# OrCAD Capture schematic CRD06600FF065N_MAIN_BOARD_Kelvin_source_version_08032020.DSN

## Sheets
1 P1 PFC: size A2; title: 6.6kW HD Bi-directional OBC Main Board; rev: 3; note: P/N: CRD06600FF065N
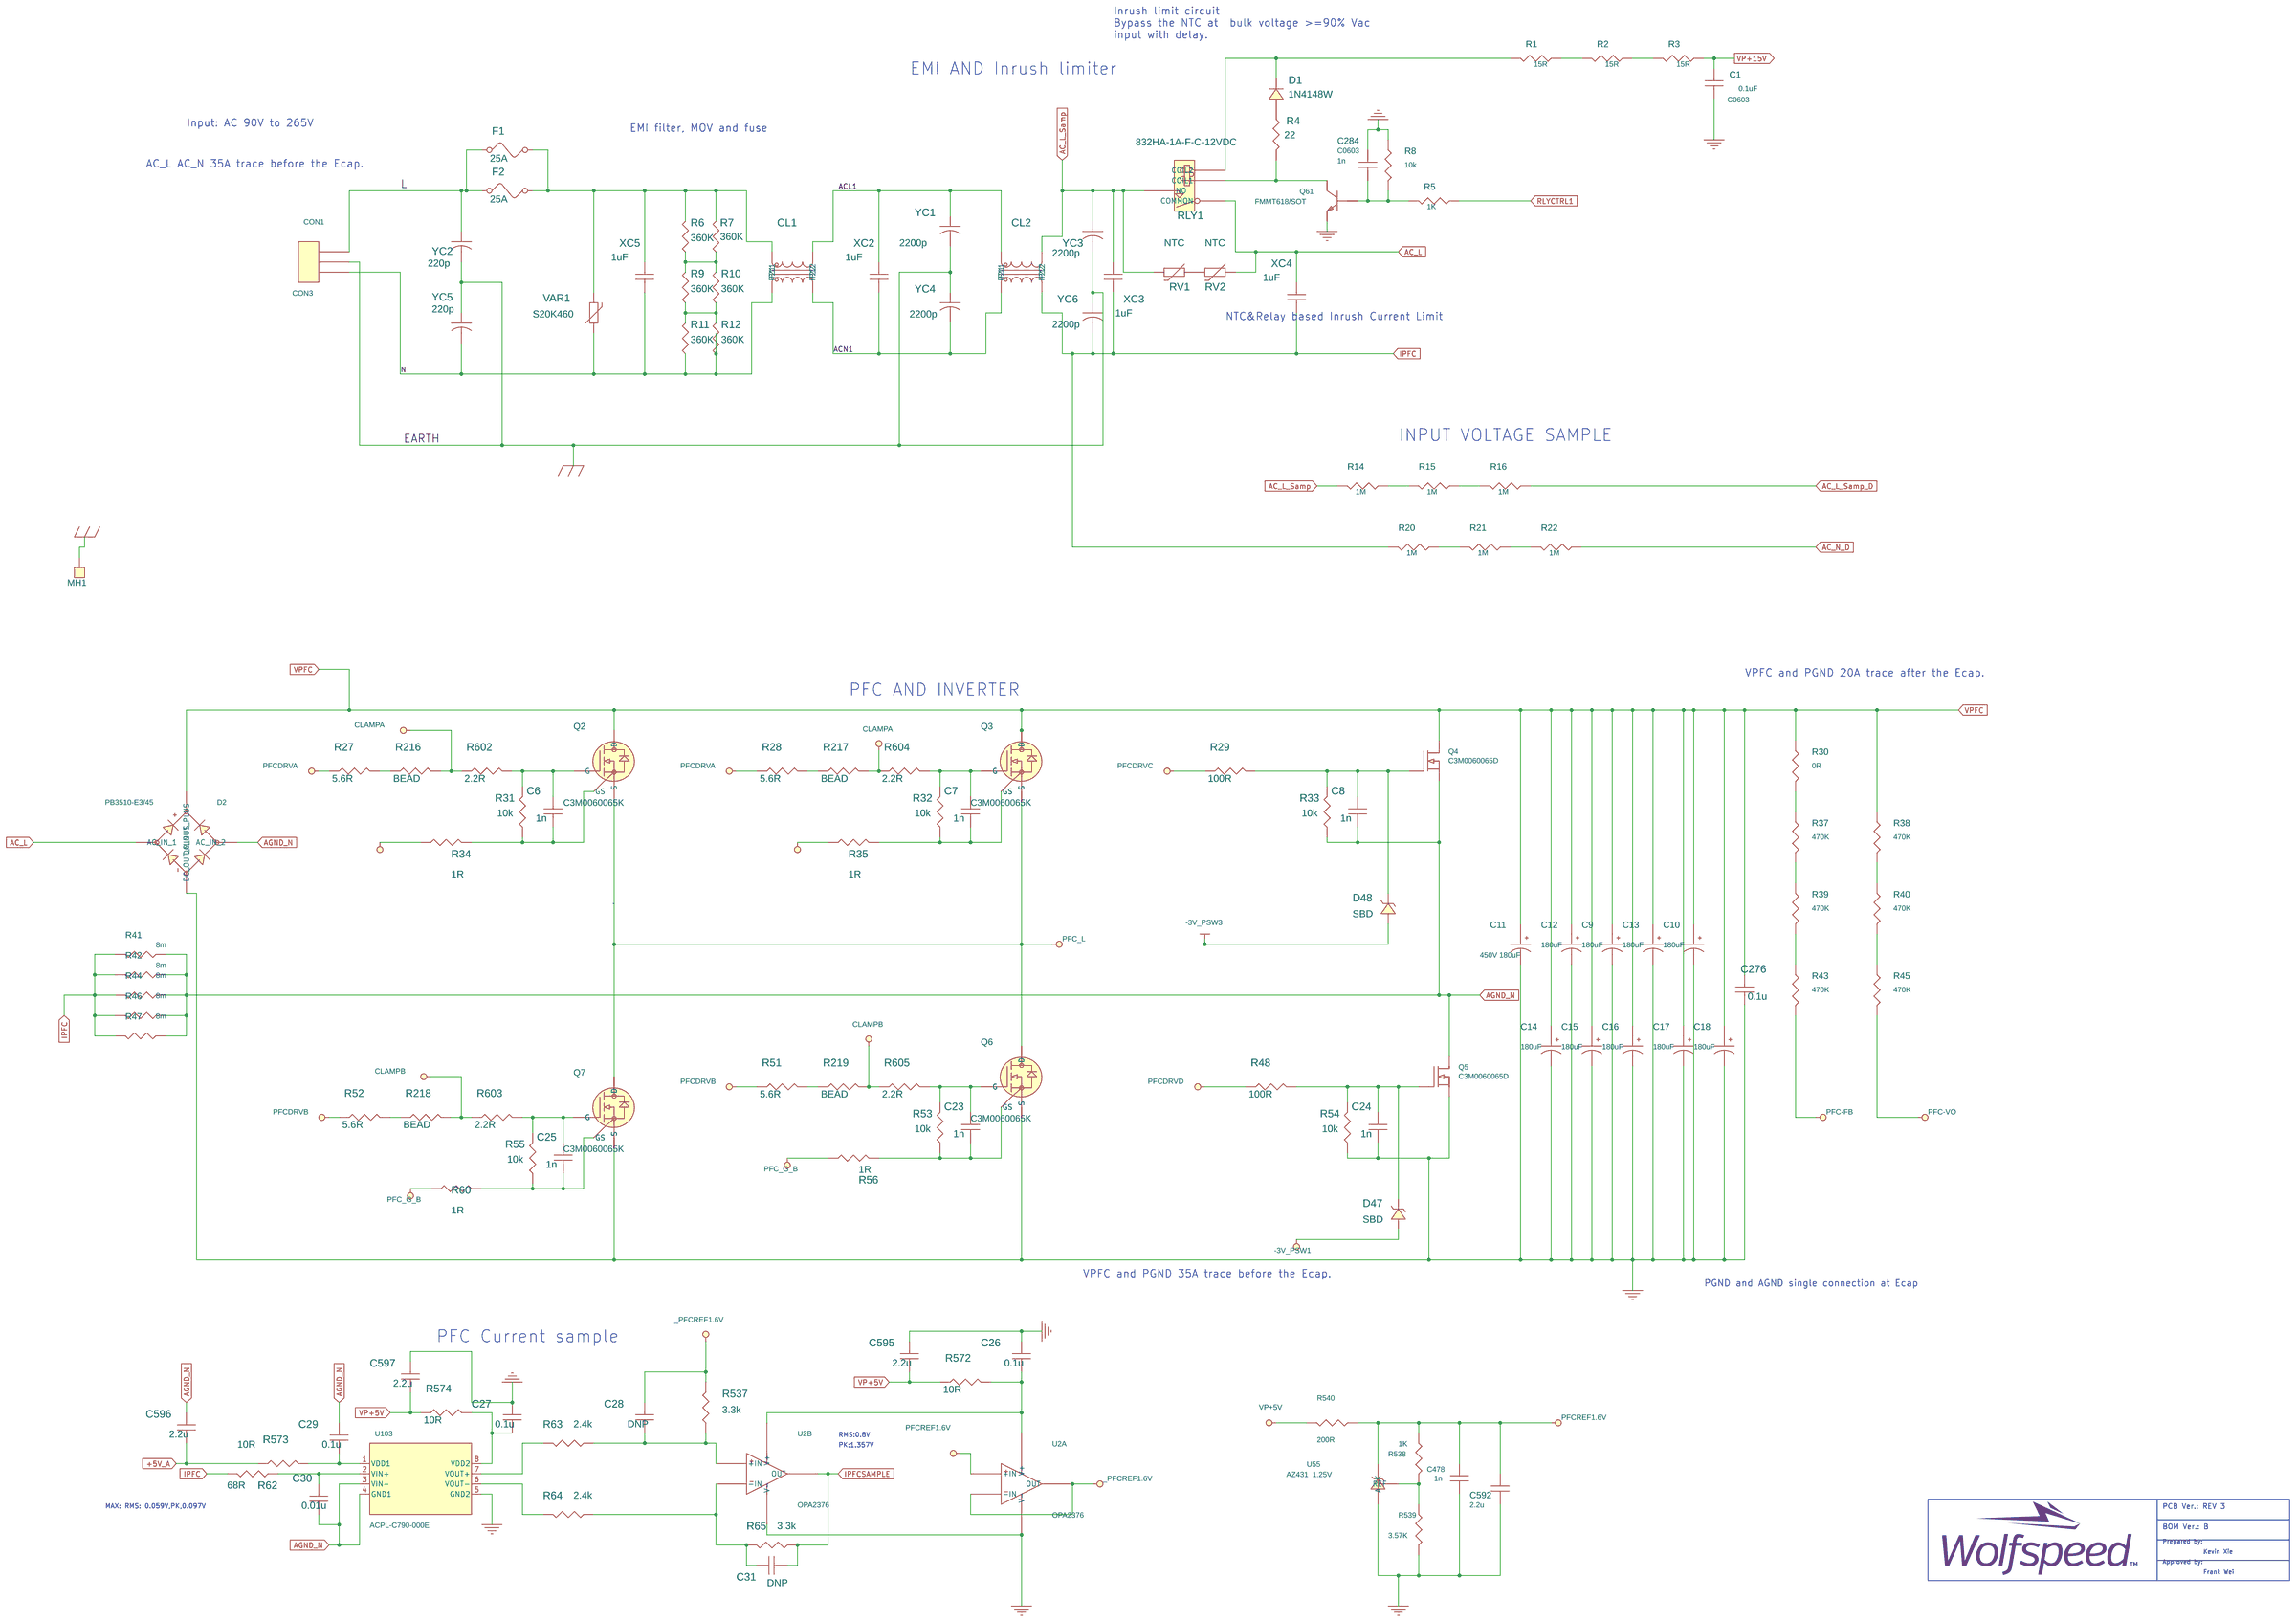
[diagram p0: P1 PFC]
2 P2 PFC Gate Driver: size A2
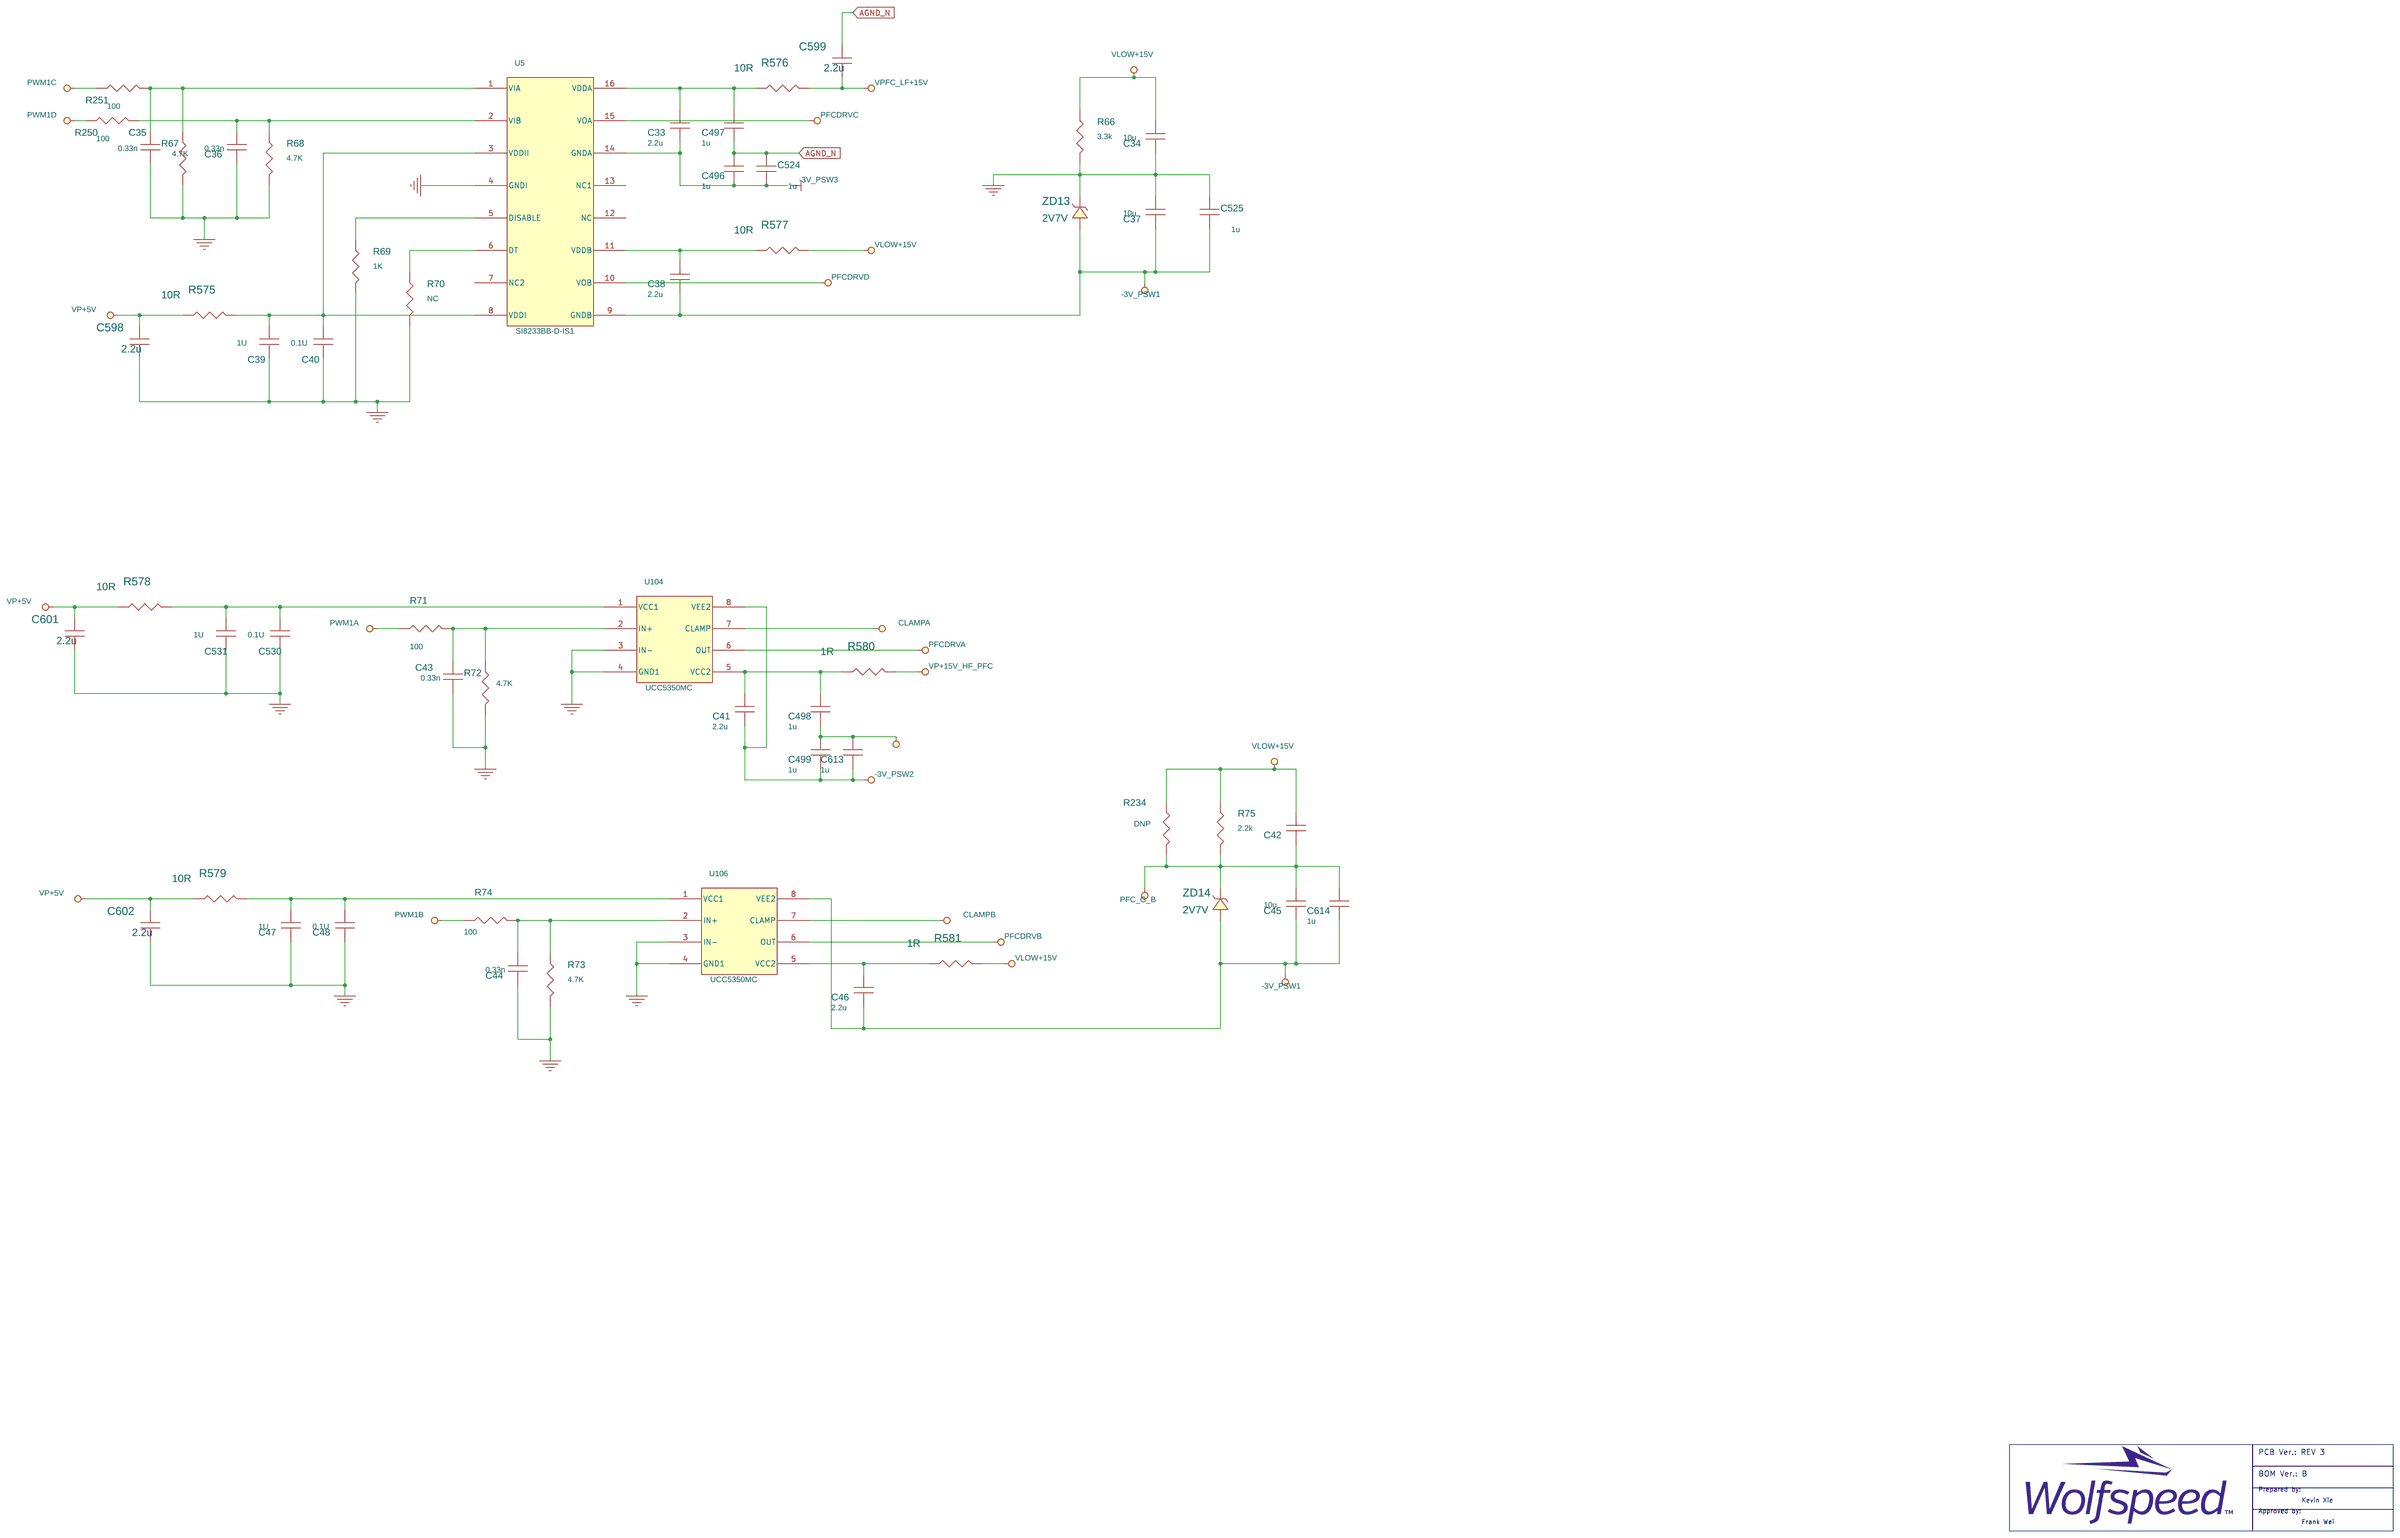
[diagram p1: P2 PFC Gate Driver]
3 P4 Main DCDC: size A1
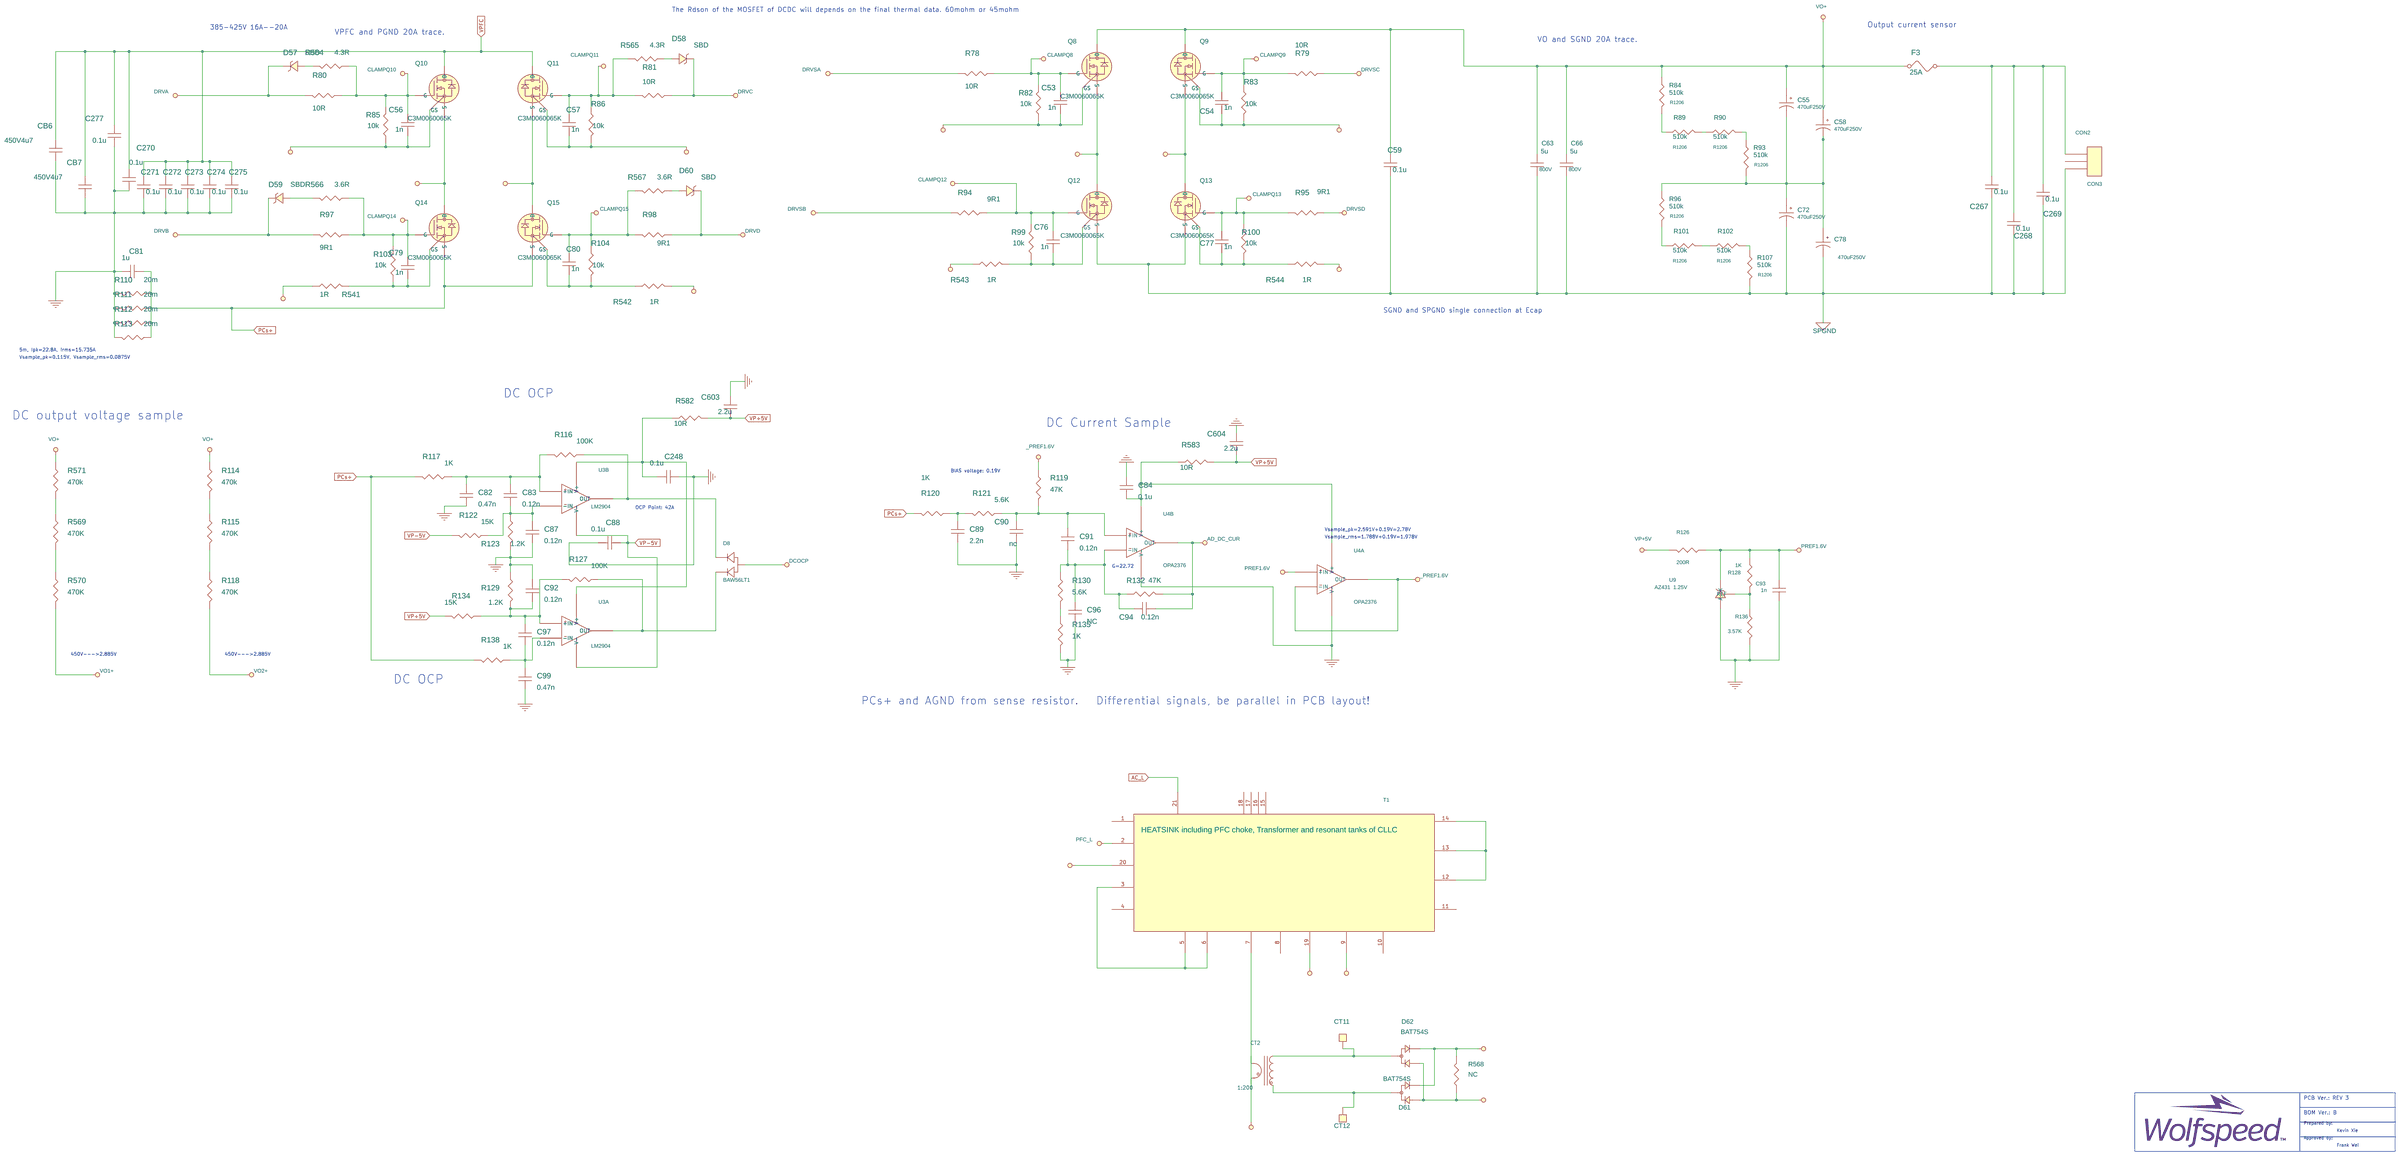
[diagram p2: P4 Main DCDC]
4 P5 Isolation Interface: size A3
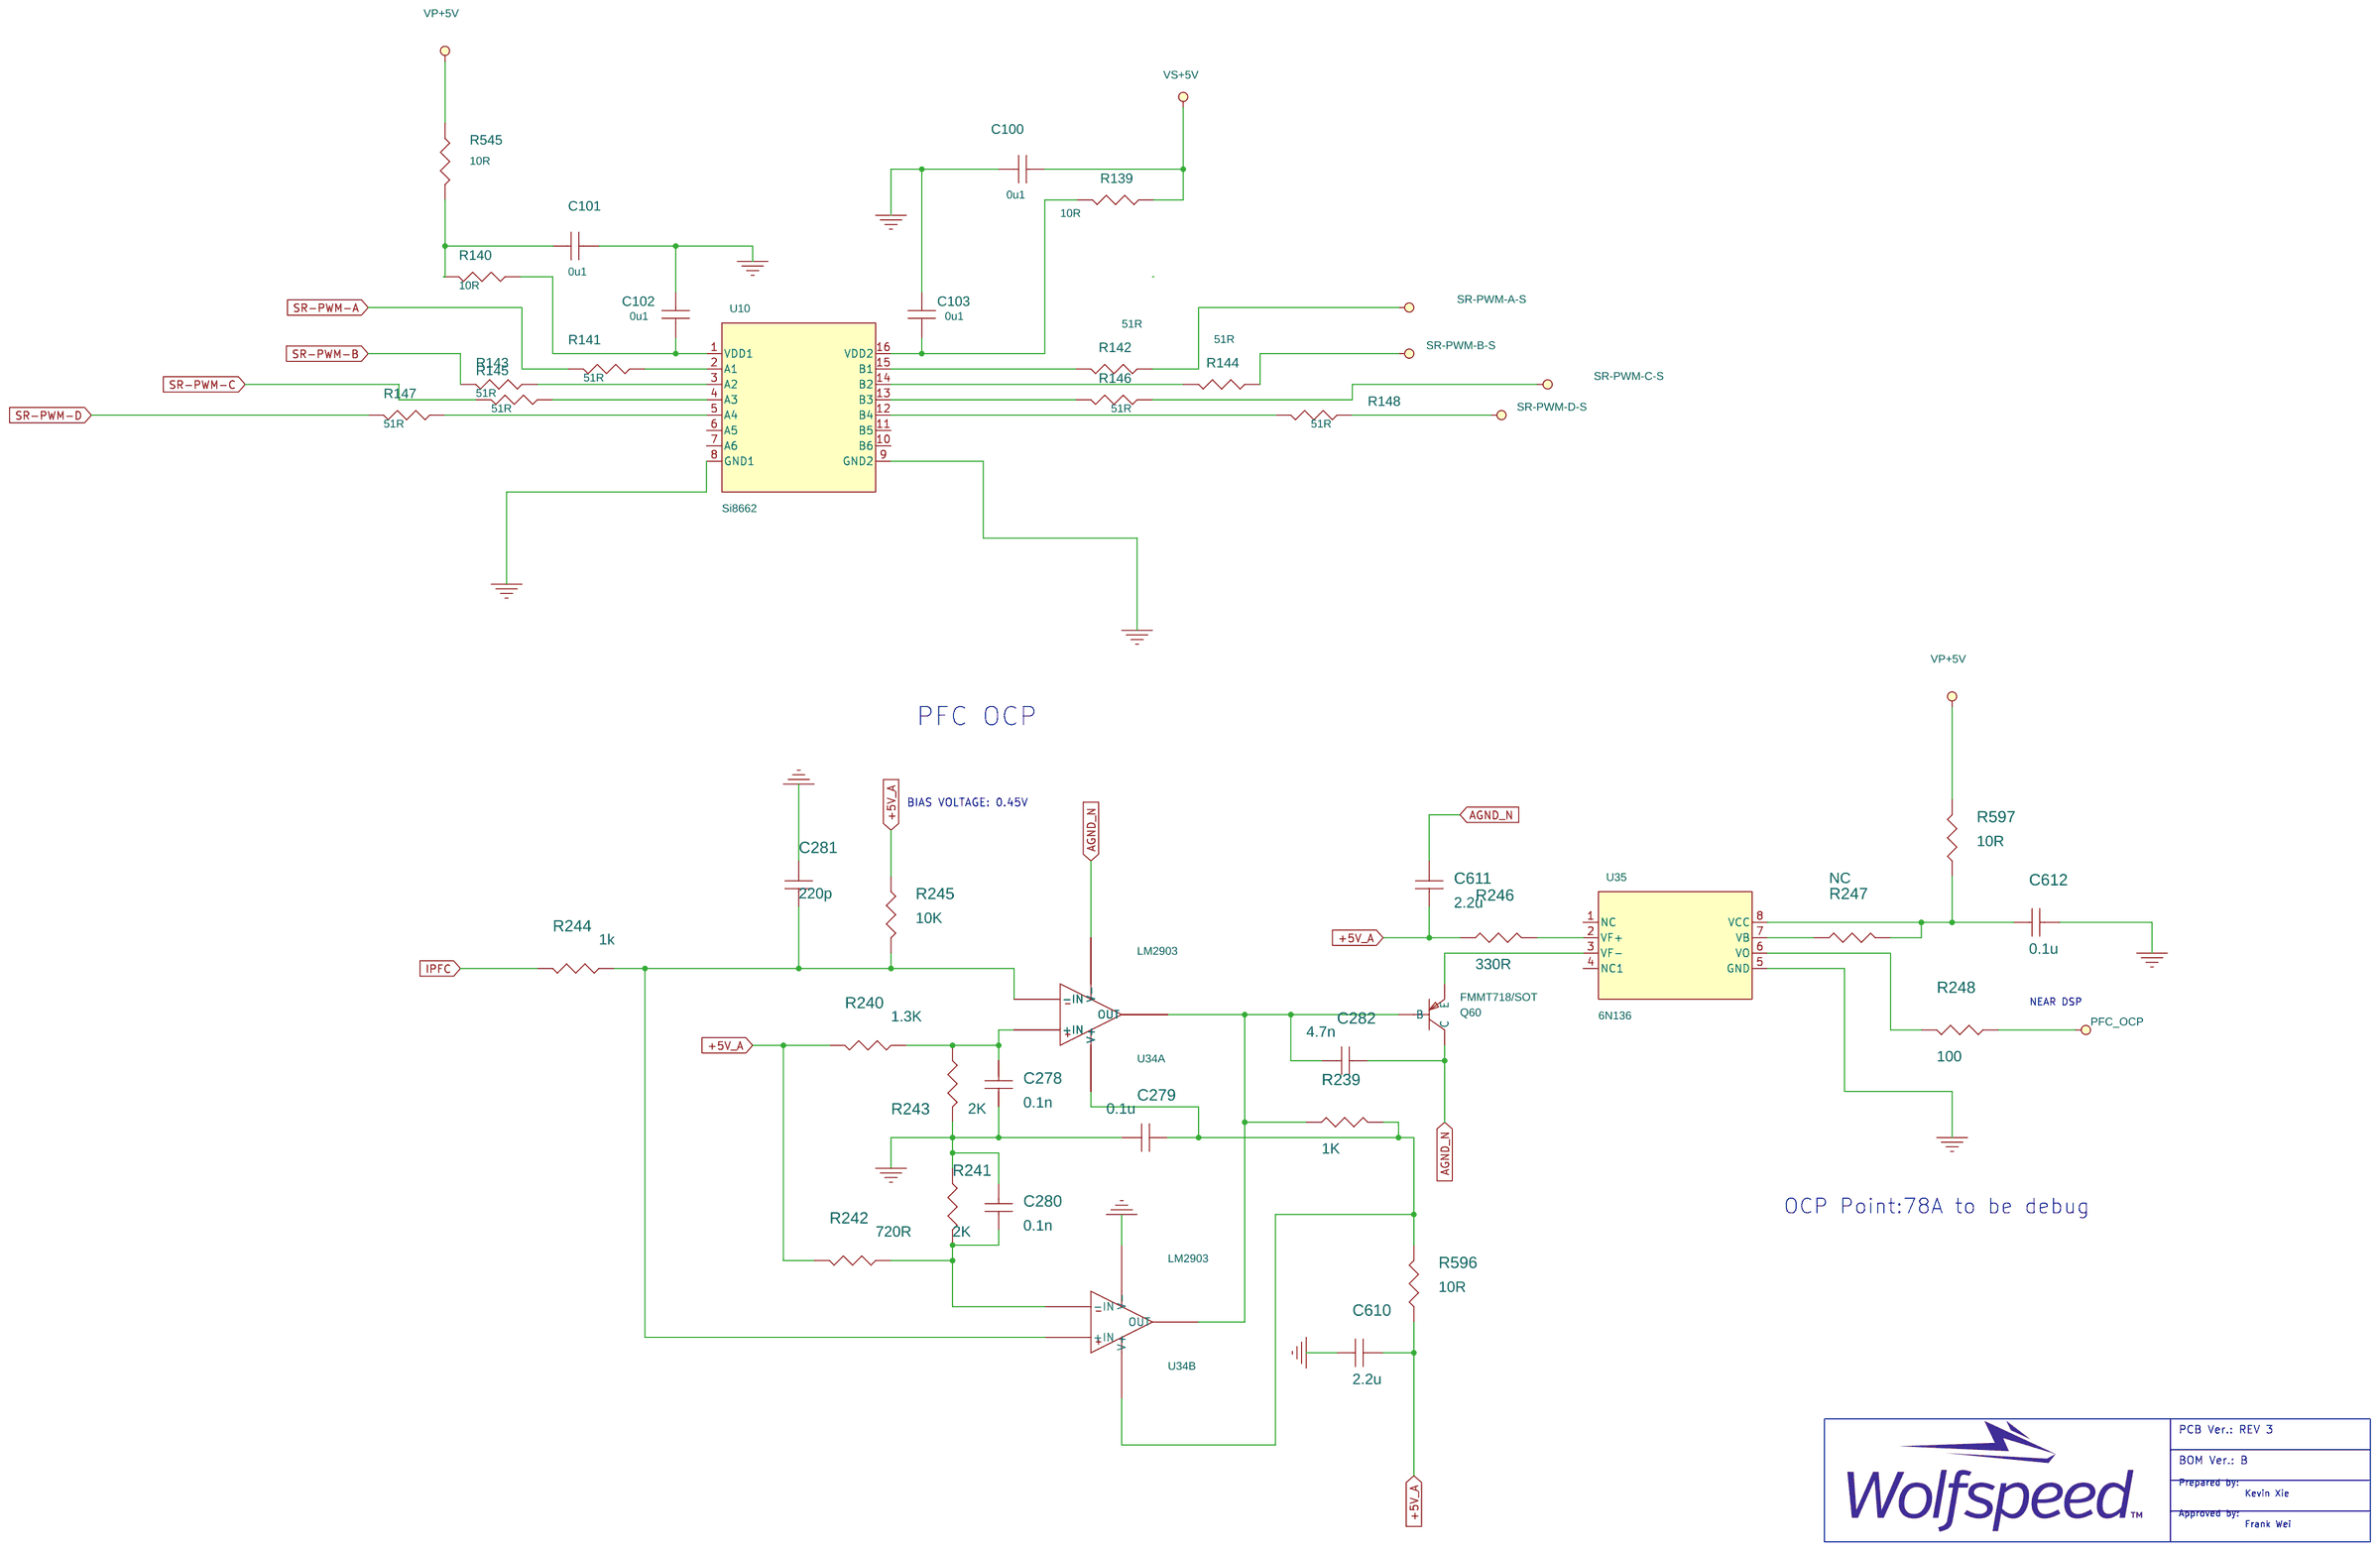
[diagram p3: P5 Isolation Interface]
5 P6 DCDC Primary Gate Driver: size A2
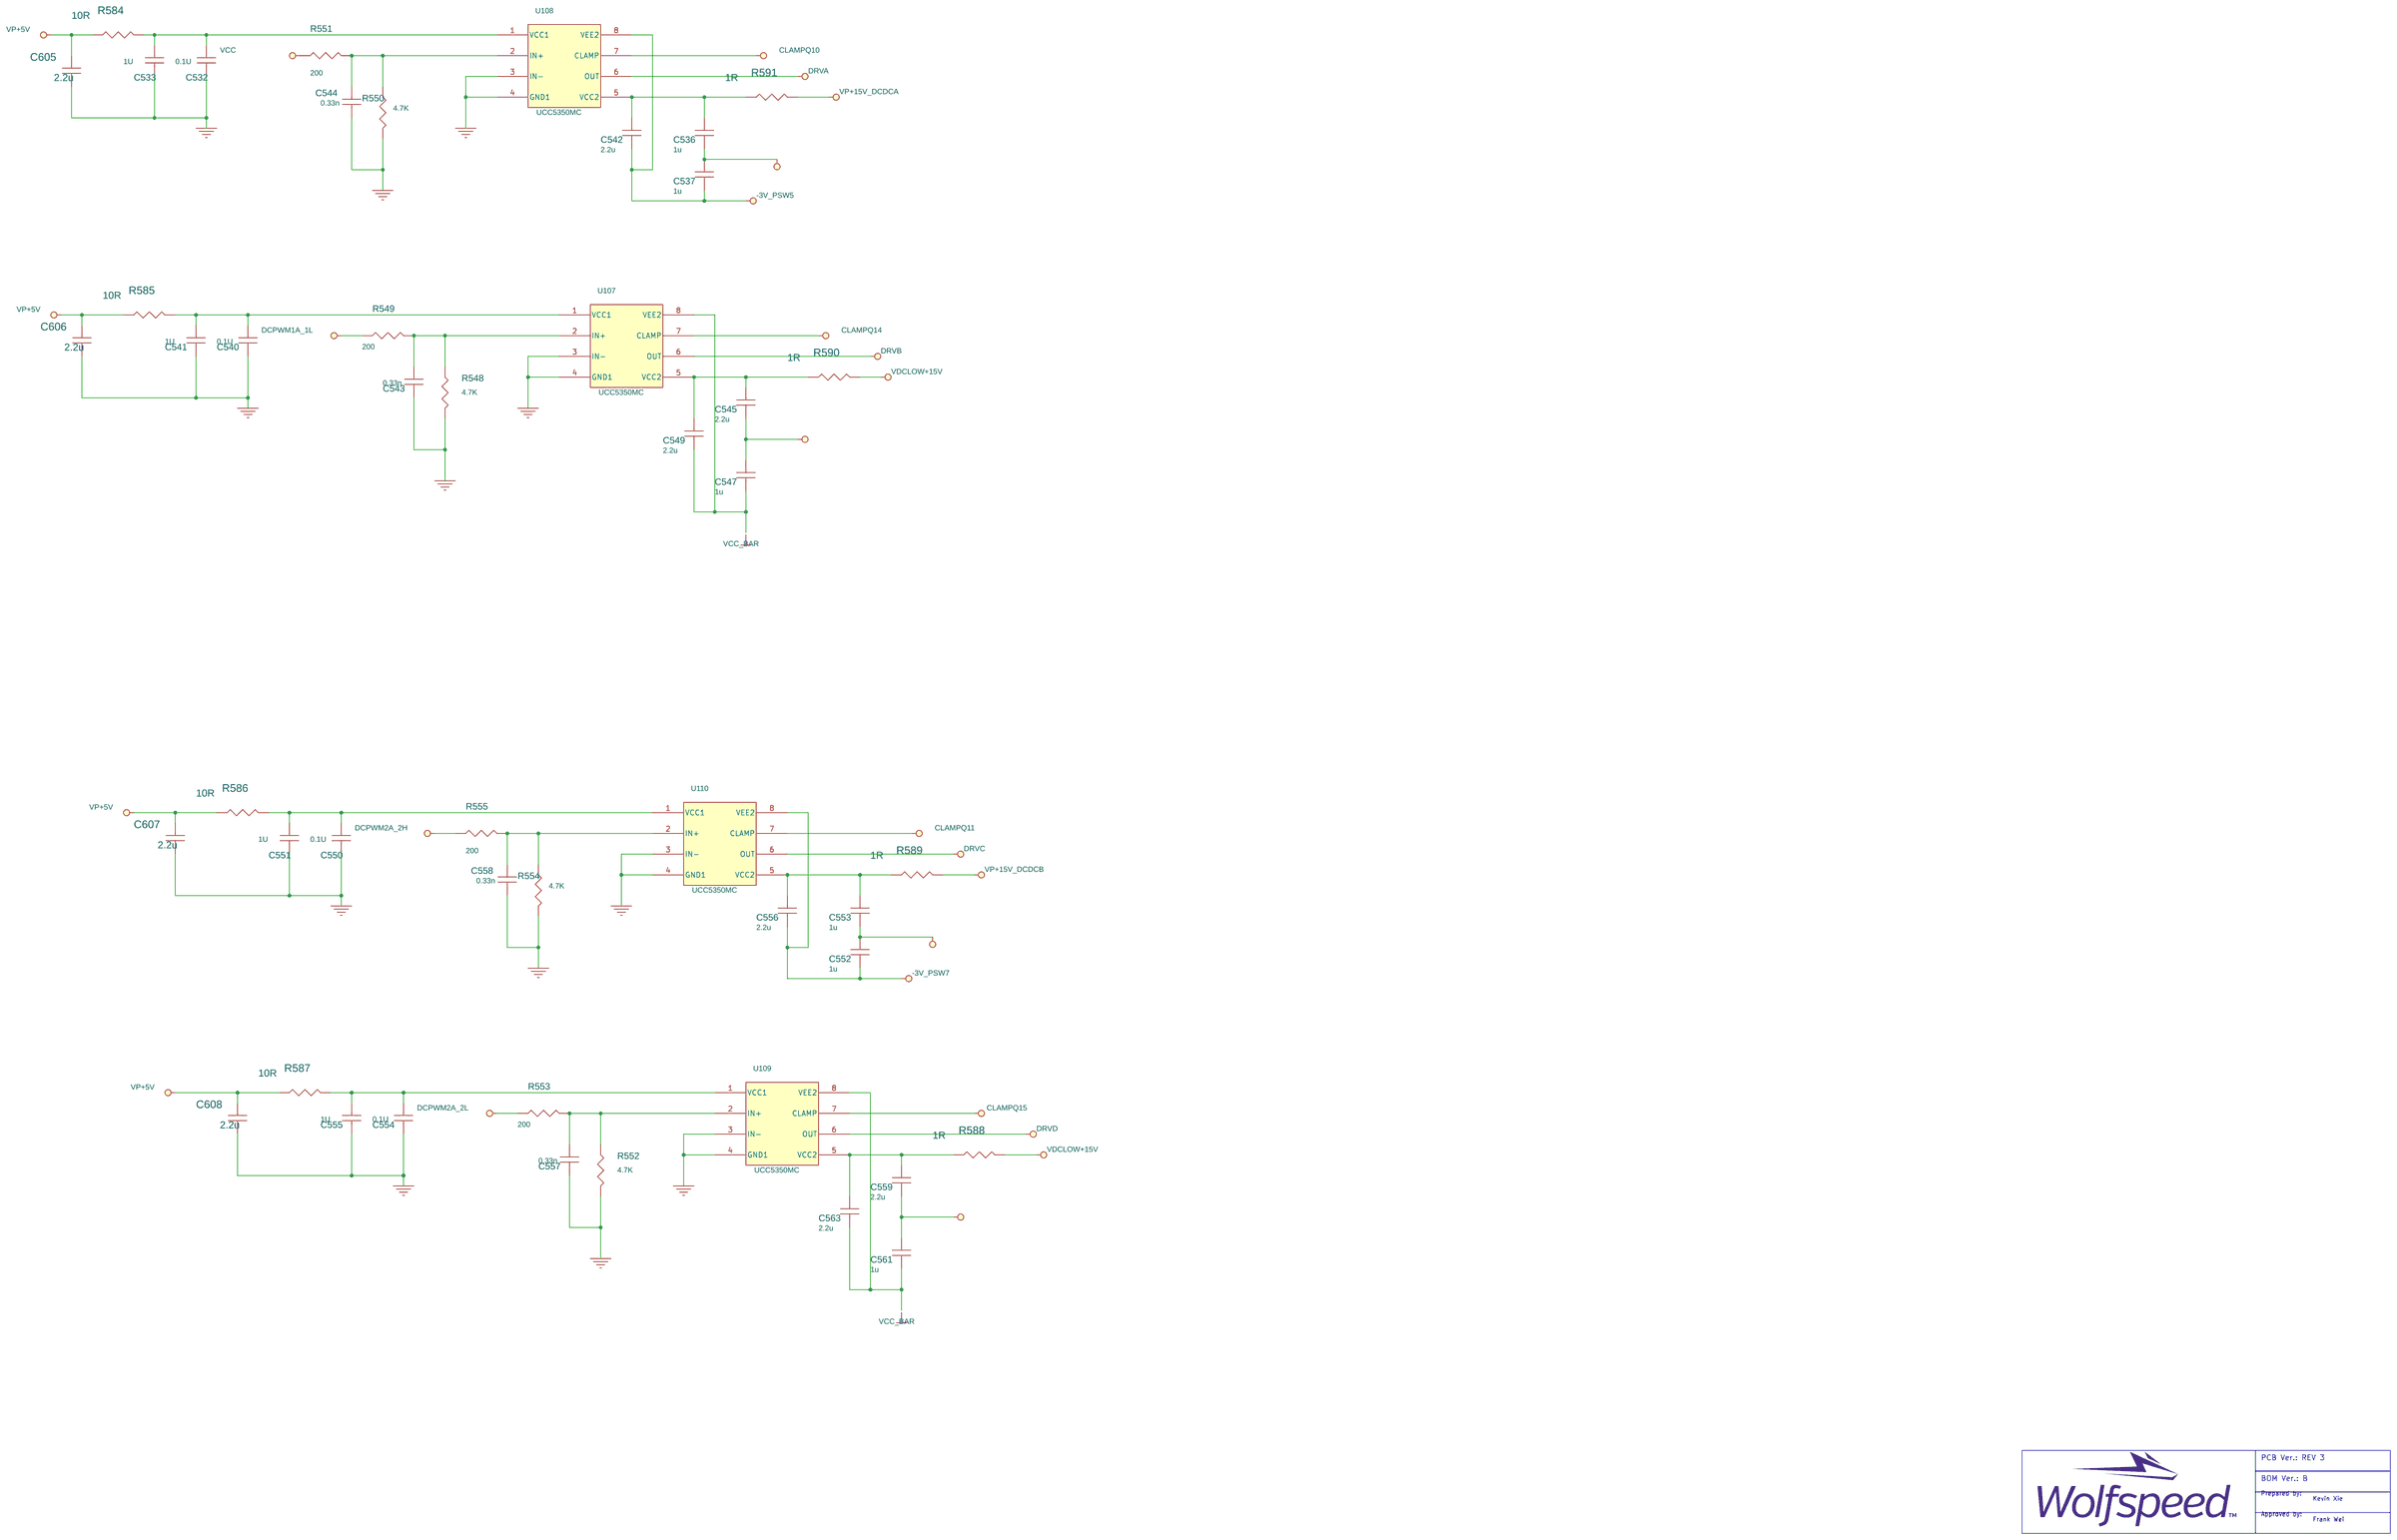
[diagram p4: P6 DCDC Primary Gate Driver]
6 P7 DCDC Secondary Gate Driver: size A2
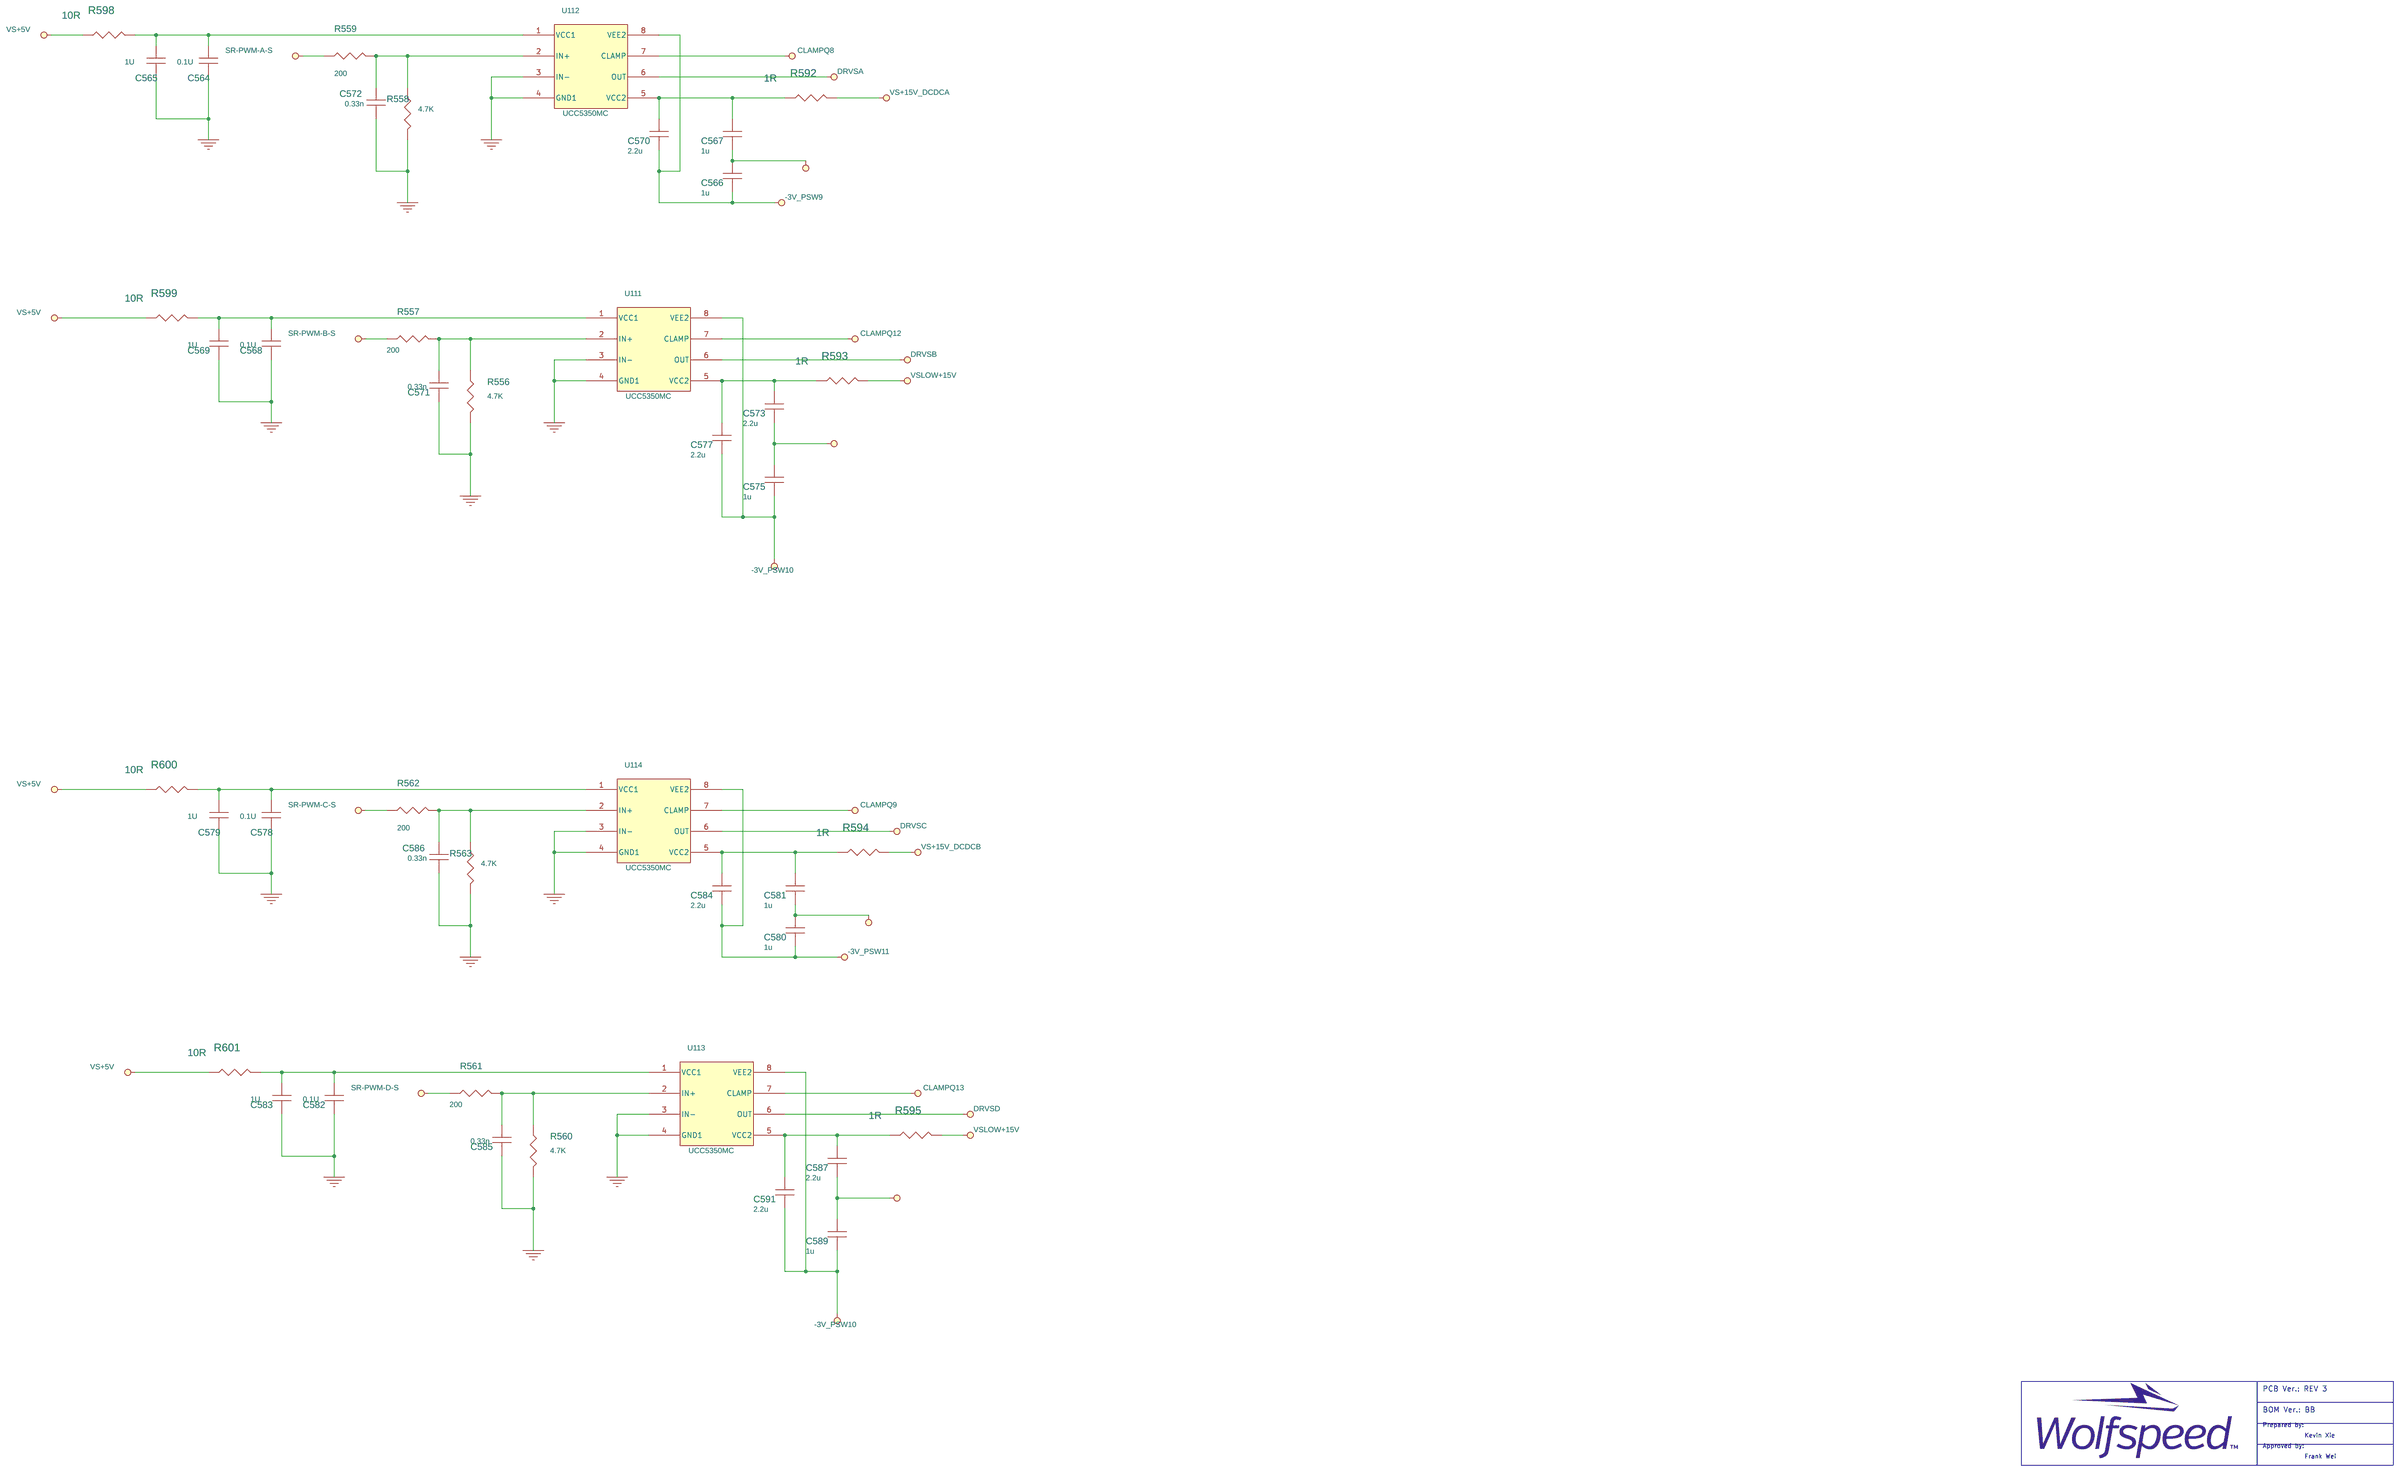
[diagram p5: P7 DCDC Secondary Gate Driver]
7 P3 Bias POWER SUPPLY: size A1
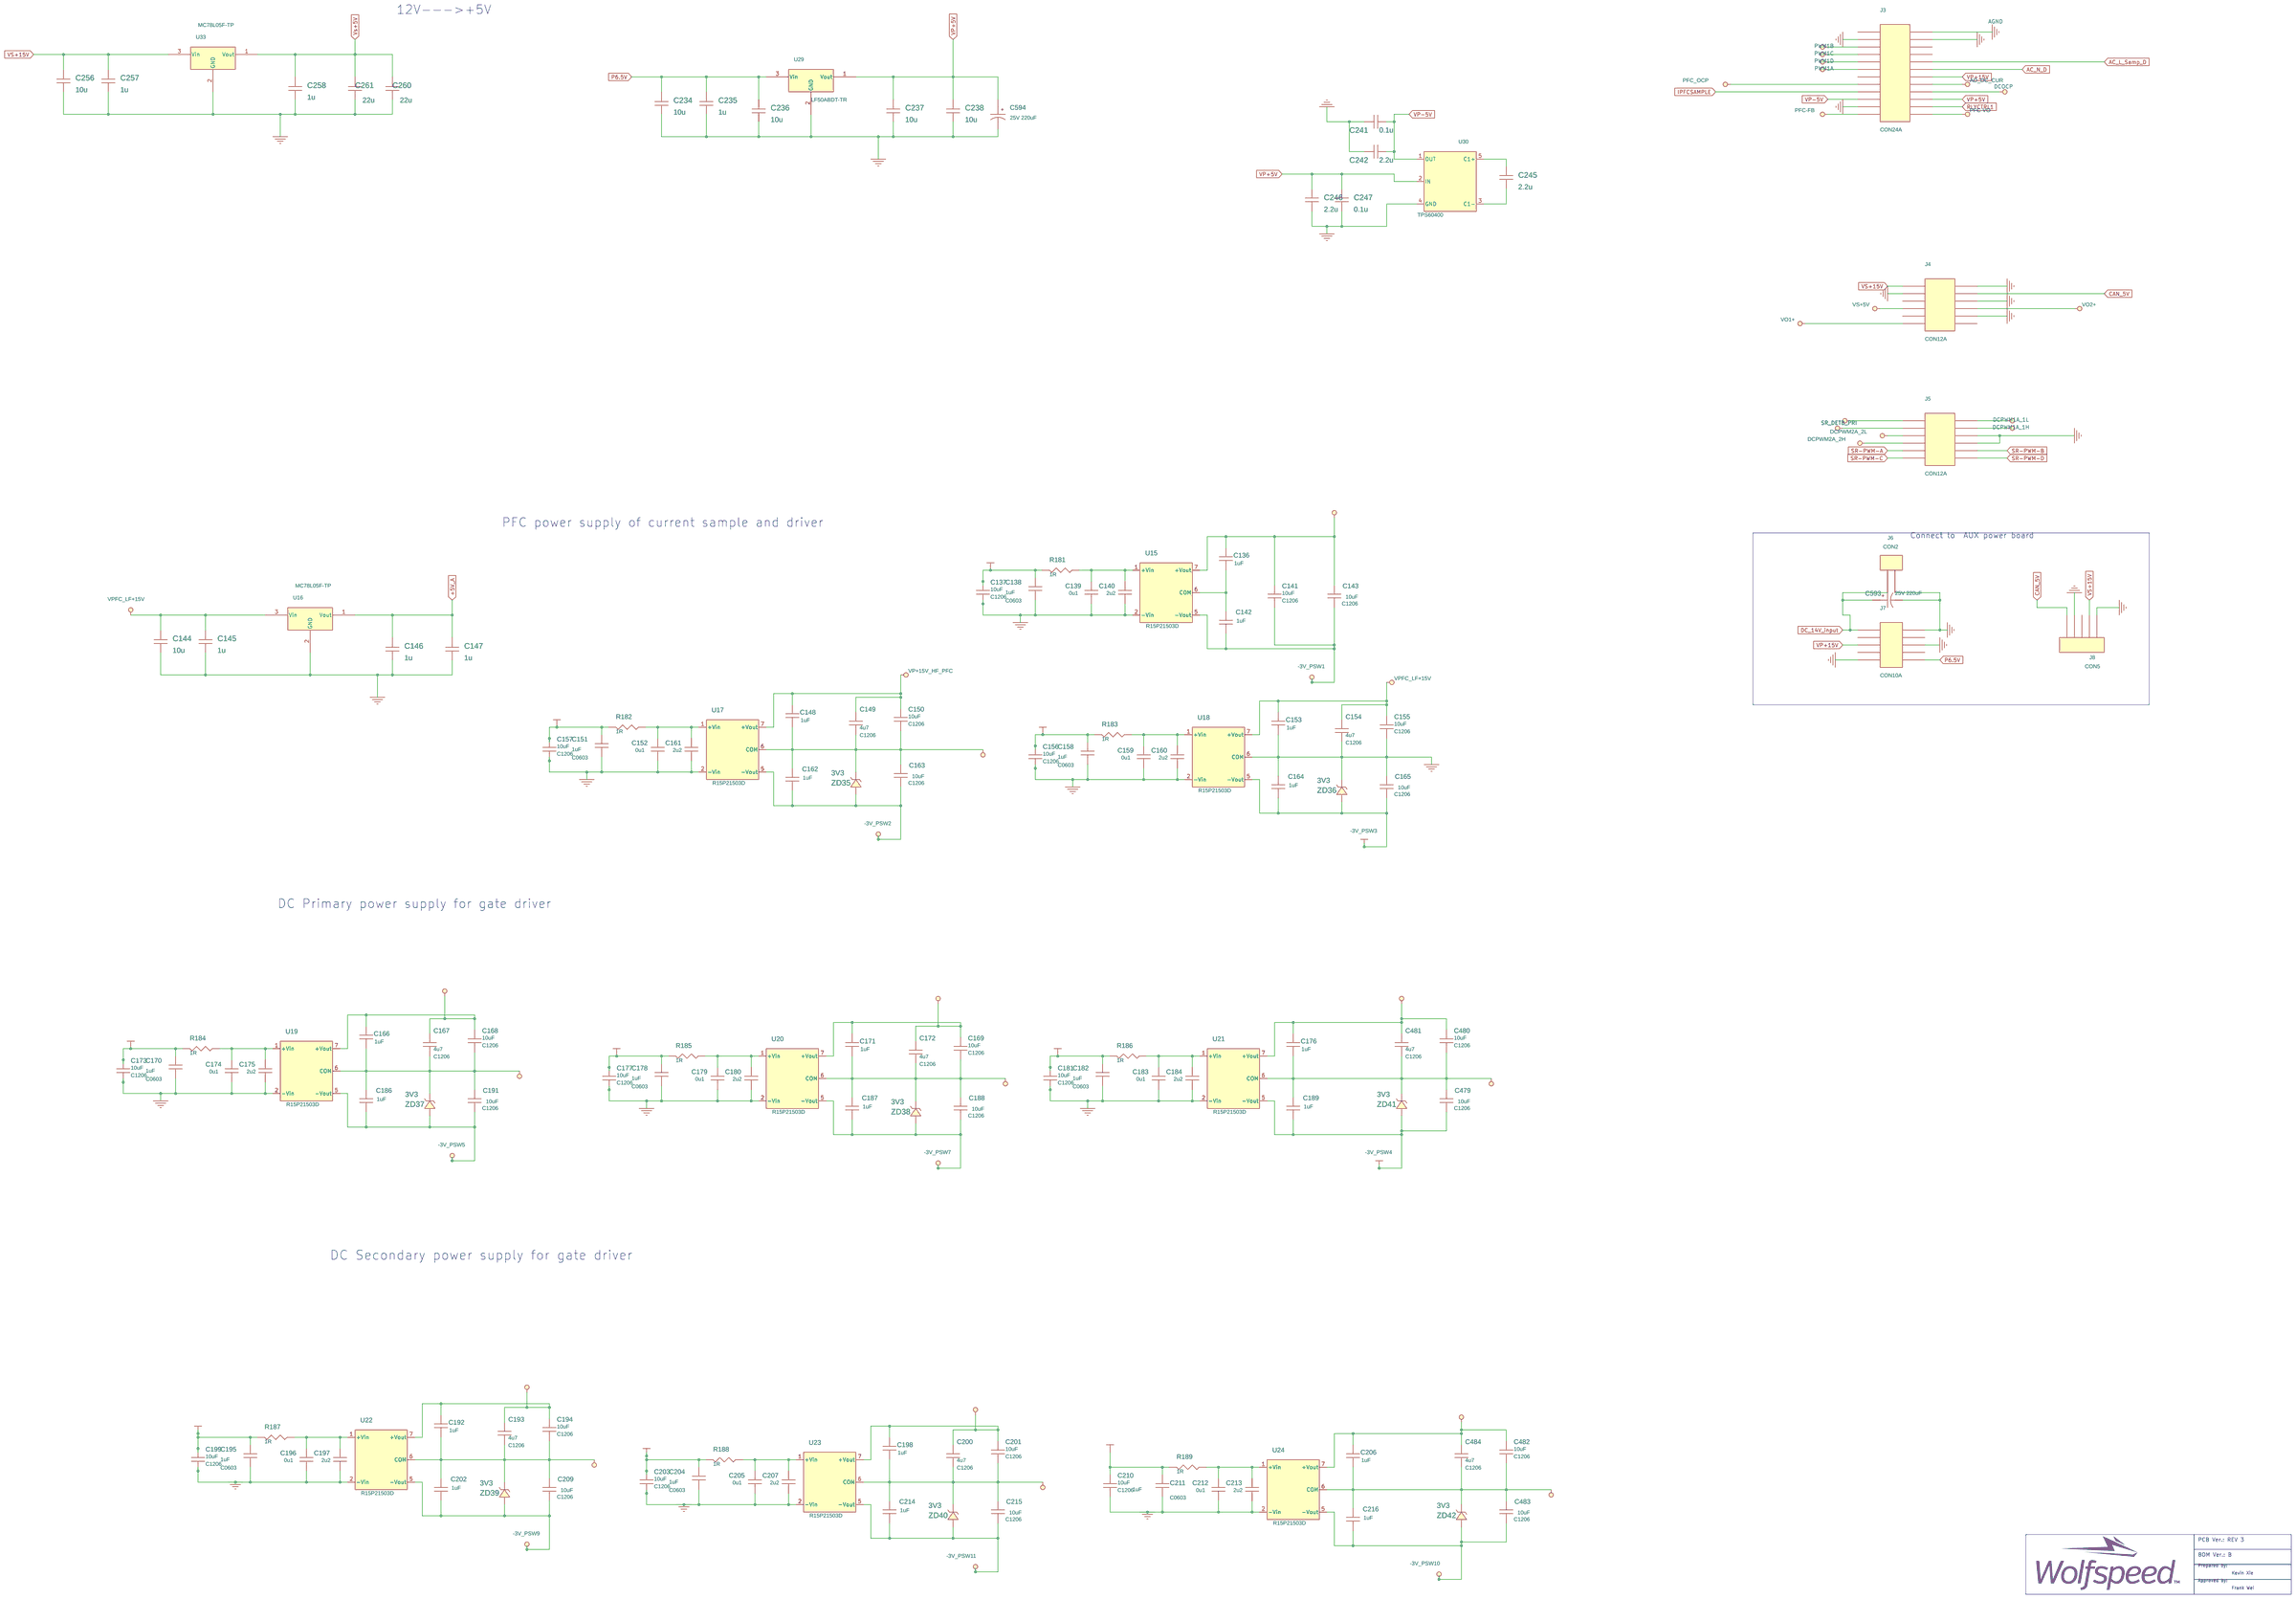
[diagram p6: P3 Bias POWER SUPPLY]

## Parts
sheet P1 PFC
C1  0.1uF  [C0603]
C6  1n  [C0603]
C7  1n  [C0603]
C8  1n  [C0603]
C9  180uF  [ecap_d18p7_5]
C10  180uF  [ecap_d18p7_5]
C11  450V 180uF  [ecap_d18p7_5]
C12  180uF  [ecap_d18p7_5]
C13  180uF  [ecap_d18p7_5]
C14  180uF  [ecap_d18p7_5]
C15  180uF  [ecap_d18p7_5]
C16  180uF  [ecap_d18p7_5]
C17  180uF  [ecap_d18p7_5]
C18  180uF  [ecap_d18p7_5]
C23  1n  [C0603]
C24  1n  [C0603]
C25  1n  [C0603]
C26  0.1u  [C0603]
C27  0.1u  [C0603]
C28  DNP  [C0603]
C29  0.1u  [C0603]
C30  0.01u  [C0603]
C31  DNP  [C0603]
C276  0.1u  [C1812]
C284  1n  [C0603]
C478  1n  [C0603]
C592  2.2u  [C0805]
C595  2.2u  [C0603]
C596  2.2u  [C0603]
C597  2.2u  [C0603]
CL1  6Ts  [CM_4P]
CL2  6Ts  [CM_4P]
CON1  CON3  [KF45-3]
D1  1N4148W  [SOD-123]
D2  PB3510-E3/45  [PB3510]
D47  SBD  [SOD-123]
D48  SBD  [SOD-123]
F1  25A  [FULSE]
F2  25A  [FULSE]
MH1  T1T2  [MTH122]
Q2  C3M0060065K  [to-247-4l]
Q3  C3M0060065K  [to-247-4l]
Q4  C3M0060065D  [TO247]
Q5  C3M0060065D  [TO247]
Q6  C3M0060065K  [to-247-4l]
Q7  C3M0060065K  [to-247-4l]
Q61  FMMT618/SOT  [SOT23]
R1  15R  [R1206]
R2  15R  [R1206]
R3  15R  [R1206]
R4  22  [R1206]
R5  1K  [R0603]
R6  360K  [R1206]
R7  360K  [R1206]
R8  10k  [R0603]
R9  360K  [R1206]
R10  360K  [R1206]
R11  360K  [R1206]
R12  360K  [R1206]
R14  1M  [R1206]
R15  1M  [R1206]
R16  1M  [R1206]
R20  1M  [R1206]
R21  1M  [R1206]
R22  1M  [R1206]
R27  5.6R  [R1206]
R28  5.6R  [R1206]
R29  100R  [R1206]
R30  0R  [R1206]
R31  10k  [R0603]
R32  10k  [R0603]
R33  10k  [R0603]
R34  1R  [R0805]
R35  1R  [R0805]
R37  470K  [R1206]
R38  470K  [R1206]
R39  470K  [R1206]
R40  470K  [R1206]
R41  8m  [R2512]
R42  8m  [R2512]
R43  470K  [R1206]
R44  8m  [R2512]
R45  470K  [R1206]
R46  8m  [R2512]
R47  8m  [R2512]
R48  100R  [R1206]
R51  5.6R  [R1206]
R52  5.6R  [R1206]
R53  10k  [R0603]
R54  10k  [R0603]
R55  10k  [R0603]
R56  1R  [R0805]
R60  1R  [R0805]
R62  68R  [R0603]
R63  2.4k  [R0603]
R64  2.4k  [R0603]
R65  3.3k  [R0603]
R216  BEAD  [R1206]
R217  BEAD  [R1206]
R218  BEAD  [R1206]
R219  BEAD  [R1206]
R537  3.3k  [R0603]
R538  1K  [R0603]
R539  3.57K  [R0603]
R540  200R  [R0603]
R572  10R  [R0603]
R573  10R  [R0603]
R574  10R  [R0603]
R602  2.2R  [R0805]
R603  2.2R  [R0805]
R604  2.2R  [R0805]
R605  2.2R  [R0805]
RLY1  832HA-1A-F-C-12VDC  [T9SV1K15-12]
RV1  NTC  [NTC_od20MM]
RV2  NTC  [NTC_od20MM]
U2  OPA2376  [SOIC8]  (sections A,B)
U55  AZ431  1.25V  [SOT-23]
U103  ACPL-C790-000E  [SSO-8]
VAR1  S20K460  [MOV_OD21P5MM_PI10MM_PINV3P3MM]
XC2  1uF  [CAPFILM_26_5X12MM]
XC3  1uF  [CAPFILM_26_5X12MM]
XC4  1uF  [CAPFILM_26_5X12MM]
XC5  1uF  [CAPFILM_26_5X12MM]
YC1  2200p  [C1812]
YC2  220p  [C1812]
YC3  2200p  [C1812]
YC4  2200p  [C1812]
YC5  220p  [C1812]
YC6  2200p  [C1812]
sheet P2 PFC Gate Driver
C33  2.2u  [C0805]
C34  10u  [C1206]
C35  0.33n  [C0603]
C36  0.33n  [C0603]
C37  10u  [C1206]
C38  2.2u  [C0805]
C39  1U  [C0603]
C40  0.1U  [C0603]
C41  2.2u  [C0805]
C42  10u  [C1206]
C43  0.33n  [C0603]
C44  0.33n  [C0603]
C45  10u  [C1206]
C46  2.2u  [C0805]
C47  1U  [C0603]
C48  0.1U  [C0603]
C496  1u  [C0603]
C497  1u  [C0603]
C498  1u  [C0603]
C499  1u  [C0603]
C524  1u  [C0603]
C525  1u  [C0603]
C530  0.1U  [C0603]
C531  1U  [C0603]
C598  2.2u  [C0603]
C599  2.2u  [C0603]
C601  2.2u  [C0603]
C602  2.2u  [C0603]
C613  1u  [C0603]
C614  1u  [C0603]
R66  3.3k  [R1206]
R67  4.7K  [R0603]
R68  4.7K  [R0603]
R69  1K  [R0603]
R70  NC  [R0603]
R71  100  [R0603]
R72  4.7K  [R0603]
R73  4.7K  [R0603]
R74  100  [R0603]
R75  2.2k  [R1206]
R234  DNP  [R1206]
R250  100  [R0603]
R251  100  [R0603]
R575  10R  [R0603]
R576  10R  [R0805]
R577  10R  [R0805]
R578  10R  [R0603]
R579  10R  [R0603]
R580  1R  [R0805]
R581  1R  [R0805]
U5  SI8233BB-D-IS1  [SOIC16-127W]
U104  UCC5350MC  [SOIC8]
U106  UCC5350MC  [SOIC8]
ZD13  2V7V  [SOD-123]
ZD14  2V7V  [SOD-123]
sheet P3 Bias POWER SUPPLY
C136  1uF  [C0603]
C137  10uF  [C1206]
C138  1uF  [C0603]
C139  0u1  [C0603]
C140  2u2  [C1206]
C141  10uF  [C1206]
C142  1uF  [C0603]
C143  10uF  [C1206]
C144  10u  [C1206]
C145  1u  [C0603]
C146  1u  [C1206]
C147  1u  [C0603]
C148  1uF  [C0603]
C149  4u7  [C1206]
C150  10uF  [C1206]
C151  1uF  [C0603]
C152  0u1  [C0603]
C153  1uF  [C0603]
C154  4u7  [C1206]
C155  10uF  [C1206]
C156  10uF  [C1206]
C157  10uF  [C1206]
C158  1uF  [C0603]
C159  0u1  [C0603]
C160  2u2  [C1206]
C161  2u2  [C1206]
C162  1uF  [C0603]
C163  10uF  [C1206]
C164  1uF  [C0603]
C165  10uF  [C1206]
C166  1uF  [C0603]
C167  4u7  [C1206]
C168  10uF  [C1206]
C169  10uF  [C1206]
C170  1uF  [C0603]
C171  1uF  [C0603]
C172  4u7  [C1206]
C173  10uF  [C1206]
C174  0u1  [C0603]
C175  2u2  [C1206]
C176  1uF  [C0603]
C177  10uF  [C1206]
C178  1uF  [C0603]
C179  0u1  [C0603]
C180  2u2  [C1206]
C181  10uF  [C1206]
C182  1uF  [C0603]
C183  0u1  [C0603]
C184  2u2  [C1206]
C186  1uF  [C0603]
C187  1uF  [C0603]
C188  10uF  [C1206]
C189  1uF  [C0603]
C191  10uF  [C1206]
C192  1uF  [C0603]
C193  4u7  [C1206]
C194  10uF  [C1206]
C195  1uF  [C0603]
C196  0u1  [C0603]
C197  2u2  [C1206]
C198  1uF  [C0603]
C199  10uF  [C1206]
C200  4u7  [C1206]
C201  10uF  [C1206]
C202  1uF  [C0603]
C203  10uF  [C1206]
C204  1uF  [C0603]
C205  0u1  [C0603]
C206  1uF  [C0603]
C207  2u2  [C1206]
C209  10uF  [C1206]
C210  10uF  [C1206]
C211  1uF  [C0603]
C212  0u1  [C0603]
C213  2u2  [C1206]
C214  1uF  [C0603]
C215  10uF  [C1206]
C216  1uF  [C0603]
C234  10u  [C1206]
C235  1u  [C0603]
C236  10u  [C1206]
C237  10u  [C1206]
C238  10u  [C1206]
C241  0.1u  [C0603]
C242  2.2u  [C0805]
C245  2.2u  [C0805]
C246  2.2u  [C0805]
C247  0.1u  [C0603]
C256  10u  [C1206]
C257  1u  [C0603]
C258  1u  [C1206]
C260  22u  [C1206]
C261  22u  [C1206]
C479  10uF  [C1206]
C480  10uF  [C1206]
C481  4u7  [C1206]
C482  10uF  [C1206]
C483  10uF  [C1206]
C484  4u7  [C1206]
C593  25V 220uF  [ecap_d8p3_5]
C594  25V 220uF  [ecap_d8p3_5]
J3  CON24A  [con_2mm54_12x2]
J4  CON12A  [con_2mm54_6x2]
J5  CON12A  [con_2mm54_6x2]
J6  CON2  [CON_5MM_2X1]
J7  CON10A  [con_2mm54_5x2]
J8  CON5  [con_2mm54_5x1]
R181  1R  [R0805]
R182  1R  [R0805]
R183  1R  [R0805]
R184  1R  [R0805]
R185  1R  [R0805]
R186  1R  [R0805]
R187  1R  [R0805]
R188  1R  [R0805]
R189  1R  [R0805]
U15  R15P21503D  [g1212s_2w11]
U16  MC78L05F-TP  [SOT-89-3L]
U17  R15P21503D  [g1212s_2w11]
U18  R15P21503D  [g1212s_2w11]
U19  R15P21503D  [g1212s_2w11]
U20  R15P21503D  [g1212s_2w11]
U21  R15P21503D  [g1212s_2w11]
U22  R15P21503D  [g1212s_2w11]
U23  R15P21503D  [g1212s_2w11]
U24  R15P21503D  [g1212s_2w11]
U29  LF50ABDT-TR  [TO252AB]
U30  TPS60400  [TSOT23-5]
U33  MC78L05F-TP  [SOT-89-3L]
ZD35  3V3  [SOD-123]
ZD36  3V3  [SOD-123]
ZD37  3V3  [SOD-123]
ZD38  3V3  [SOD-123]
ZD39  3V3  [SOD-123]
ZD40  3V3  [SOD-123]
ZD41  3V3  [SOD-123]
ZD42  3V3  [SOD-123]
sheet P4 Main DCDC
C53  1n  [C0603]
C54  1n  [C0603]
C55  470uF250V  [ecap_d18p7_5]
C56  1n  [C0603]
C57  1n  [C0603]
C58  470uF250V  [ecap_d18p7_5]
C59  0.1u  [C1812]
C63  5u  [capfilm_31_5x12_5mm]
C66  5u  [capfilm_31_5x12_5mm]
C72  470uF250V  [ecap_d18p7_5]
C76  1n  [C0603]
C77  1n  [C0603]
C78  470uF250V  [ecap_d18p7_5]
C79  1n  [C0603]
C80  1n  [C0603]
C81  1u  [C0603]
C82  0.47n  [C0603]
C83  0.12n  [C0603]
C84  0.1u  [C0603]
C87  0.12n  [C0603]
C88  0.1u  [C0603]
C89  2.2n  [C0603]
C90  nc  [C0603]
C91  0.12n  [C0603]
C92  0.12n  [C0603]
C93  1n  [C0603]
C94  0.12n  [C0603]
C96  NC  [C0603]
C97  0.12n  [C0603]
C99  0.47n  [C0603]
C248  0.1u  [C0603]
C267  0.1u  [C1812]
C268  0.1u  [C1812]
C269  0.1u  [C1812]
C270  0.1u  [C1812]
C271  0.1u  [C1812]
C272  0.1u  [C1812]
C273  0.1u  [C1812]
C274  0.1u  [C1812]
C275  0.1u  [C1812]
C277  0.1u  [C1812]
C603  2.2u  [C0603]
C604  2.2u  [C0603]
CB6  450V4u7  [CAPFILM_26_5X12MM]
CB7  450V4u7  [CAPFILM_26_5X12MM]
CON2  CON3  [KF45-3]
CT2  1:200  [NO]
CT11  T1T2  [TH47_CR98]
CT12  T1T2  [TH47_CR98]
D8  BAW56LT1  [sot23]
D57  SBD  [SOD-123]
D58  SBD  [SOD-123]
D59  SBD  [SOD-123]
D60  SBD  [SOD-123]
D61  BAT754S  [SOT-23]
D62  BAT754S  [SOT-23]
F3  25A  [FULSE]
Q8  C3M0060065K  [to-247-4l]
Q9  C3M0060065K  [to-247-4l]
Q10  C3M0060065K  [to-247-4l]
Q11  C3M0060065K  [to-247-4l]
Q12  C3M0060065K  [to-247-4l]
Q13  C3M0060065K  [to-247-4l]
Q14  C3M0060065K  [to-247-4l]
Q15  C3M0060065K  [to-247-4l]
R78  10R  [R1206]
R79  10R  [R1206]
R80  10R  [R1206]
R81  10R  [R1206]
R82  10k  [R0603]
R83  10k  [R0603]
R84  510k  [R1206]
R85  10k  [R0603]
R86  10k  [R0603]
R89  510k  [R1206]
R90  510k  [R1206]
R93  510k  [R1206]
R94  9R1  [R1206]
R95  9R1  [R1206]
R96  510k  [R1206]
R97  9R1  [R1206]
R98  9R1  [R1206]
R99  10k  [R0603]
R100  10k  [R0603]
R101  510k  [R1206]
R102  510k  [R1206]
R103  10k  [R0603]
R104  10k  [R0603]
R107  510k  [R1206]
R110  20m  [R2512]
R111  20m  [R2512]
R112  20m  [R2512]
R113  20m  [R2512]
R114  470k  [R1206]
R115  470K  [R1206]
R116  100K  [R0603]
R117  1K  [R0603]
R118  470K  [R1206]
R119  47K  [R0603]
R120  1K  [R0603]
R121  5.6K  [R0603]
R122  15K  [R0603]
R123  1.2K  [R0603]
R126  200R  [R0603]
R127  100K  [R0603]
R128  1K  [R0603]
R129  1.2K  [R0603]
R130  5.6K  [R0603]
R132  47K  [R0603]
R134  15K  [R0603]
R135  1K  [R0603]
R136  3.57K  [R0603]
R138  1K  [R0603]
R541  1R  [R0805]
R542  1R  [R0805]
R543  1R  [R0805]
R544  1R  [R0805]
R564  4.3R  [R1206]
R565  4.3R  [R1206]
R566  3.6R  [R1206]
R567  3.6R  [R1206]
R568  NC  [R1206]
R569  470K  [R1206]
R570  470K  [R1206]
R571  470k  [R1206]
R582  10R  [R0603]
R583  10R  [R0603]
T1  HEATSINK including PFC choke, Transformer and resonant tanks of CLLC  [HEATSINK20]
U3  LM2904  [SOIC8]  (sections A,B)
U4  OPA2376  [SOIC8]  (sections A,B)
U9  AZ431  1.25V  [SOT-23]
sheet P5 Isolation Interface
C100  0u1  [C0603]
C101  0u1  [C0603]
C102  0u1  [C0603]
C103  0u1  [C0603]
C278  0.1n  [C0603]
C279  0.1u  [C0603]
C280  0.1n  [C0603]
C281  220p  [C0603]
C282  4.7n  [C0603]
C610  2.2u  [C0603]
C611  2.2u  [C0603]
C612  0.1u  [C0603]
Q60  FMMT718/SOT  [SOT23]
R139  10R  [R0603]
R140  10R  [R0603]
R141  51R  [R0603]
R142  51R  [R0603]
R143  51R  [R0603]
R144  51R  [R0603]
R145  51R  [R0603]
R146  51R  [R0603]
R147  51R  [R0603]
R148  51R  [R0603]
R239  1K  [R0603]
R240  1.3K  [R0603]
R241  2K  [R0603]
R242  720R  [R0603]
R243  2K  [R0603]
R244  1k  [R0603]
R245  10K  [R0603]
R246  330R  [R0603]
R247  NC  [R0603]
R248  100  [R0603]
R545  10R  [R0603]
R596  10R  [R0603]
R597  10R  [R0603]
U10  Si8662  [WB_SOIC16]
U34  LM2903  [SOIC8]  (sections A,B)
U35  6N136  [SOO8]
sheet P6 DCDC Primary Gate Driver
C532  0.1U  [C0603]
C533  1U  [C0603]
C536  1u  [C0603]
C537  1u  [C0603]
C540  0.1U  [C0603]
C541  1U  [C0603]
C542  2.2u  [C0805]
C543  0.33n  [C0603]
C544  0.33n  [C0603]
C545  2.2u  [C0805]
C547  1u  [C0603]
C549  2.2u  [C0805]
C550  0.1U  [C0603]
C551  1U  [C0603]
C552  1u  [C0603]
C553  1u  [C0603]
C554  0.1U  [C0603]
C555  1U  [C0603]
C556  2.2u  [C0805]
C557  0.33n  [C0603]
C558  0.33n  [C0603]
C559  2.2u  [C0805]
C561  1u  [C0603]
C563  2.2u  [C0805]
C605  2.2u  [C0603]
C606  2.2u  [C0603]
C607  2.2u  [C0603]
C608  2.2u  [C0603]
R548  4.7K  [R0603]
R549  200  [R0603]
R550  4.7K  [R0603]
R551  200  [R0603]
R552  4.7K  [R0603]
R553  200  [R0603]
R554  4.7K  [R0603]
R555  200  [R0603]
R584  10R  [R0603]
R585  10R  [R0603]
R586  10R  [R0603]
R587  10R  [R0603]
R588  1R  [R0805]
R589  1R  [R0805]
R590  1R  [R0805]
R591  1R  [R0805]
U107  UCC5350MC  [SOIC8]
U108  UCC5350MC  [SOIC8]
U109  UCC5350MC  [SOIC8]
U110  UCC5350MC  [SOIC8]
sheet P7 DCDC Secondary Gate Driver
C564  0.1U  [C0603]
C565  1U  [C0603]
C566  1u  [C0603]
C567  1u  [C0603]
C568  0.1U  [C0603]
C569  1U  [C0603]
C570  2.2u  [C0805]
C571  0.33n  [C0603]
C572  0.33n  [C0603]
C573  2.2u  [C0805]
C575  1u  [C0603]
C577  2.2u  [C0805]
C578  0.1U  [C0603]
C579  1U  [C0603]
C580  1u  [C0603]
C581  1u  [C0603]
C582  0.1U  [C0603]
C583  1U  [C0603]
C584  2.2u  [C0805]
C585  0.33n  [C0603]
C586  0.33n  [C0603]
C587  2.2u  [C0805]
C589  1u  [C0603]
C591  2.2u  [C0805]
R556  4.7K  [R0603]
R557  200  [R0603]
R558  4.7K  [R0603]
R559  200  [R0603]
R560  4.7K  [R0603]
R561  200  [R0603]
R562  200  [R0603]
R563  4.7K  [R0603]
R592  1R  [R0805]
R593  1R  [R0805]
R594  1R  [R0805]
R595  1R  [R0805]
R598  10R  [R0603]
R599  10R  [R0603]
R600  10R  [R0603]
R601  10R  [R0603]
U111  UCC5350MC  [SOIC8]
U112  UCC5350MC  [SOIC8]
U113  UCC5350MC  [SOIC8]
U114  UCC5350MC  [SOIC8]

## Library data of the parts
C1 C6-C8 C23-C31 C33-C48 C53 C54 C56 C57 C59 C76 C77 C79-C84 C87-C94 C96 C97 C99-C103 C136-C184 C186-C189 C191-C207 C209-C216 C234-C238 C241 C242 C245-C248 C256-C258 C260 C261 C267-C282 C284 C478-C484 C496-C499 C524 C525 C530-C533 C536 C537 C540-C545 C547 C549-C559 C561 C563-C573 C575 C577-C587 C589 C591 C592 C595-C599 C601-C608 C610-C614 CB6 CB7 XC2-XC5 = CAP_NP
C9-C18 C55 C58 C72 C78 C593 C594 = CAP_POL
CL1 CL2 = TRNSFMR_67125450_0
CON1 CON2 = CON3
D1 = DIODE_0
D2 = BR805D
D47 D48 D57-D60 ZD13 ZD14 ZD35-ZD42 = DIODE_ZENER_0
F1-F3 = FUSE_0
CT11 CT12 MH1 = CON1_2
Q2 Q3 Q6-Q15 = C3M0065090J_4
Q4 Q5 = MOSFET_N
Q61 = FMMT618_SOT
R1-R5 R8 R14-R16 R20-R22 R30 R37-R47 R66-R75 R84 R89 R90 R93 R96 R101 R102 R107 R139-R148 R181-R189 R234 R250 R251 R545 R548-R563 R568 = RESISTOR
R6 R9 R11 R12 = R_2
R7 = R_0
R10 = R_1
R27-R29 R31-R35 R48 R51-R56 R60 R62-R65 R78-R83 R85 R86 R94 R95 R97-R100 R103 R104 R110-R123 R126-R130 R132 R134-R136 R138 R216-R219 R239-R248 R537-R544 R564-R567 R569-R605 = R
RLY1 = RELAY_SPST_1
RV1 RV2 VAR1 = VARISTOR
U2 = LM293A: Package: 1
U9 U55 = LEU094_ZTL431AFTA_SOT23_0: LLF Part Number: LEU072
U103 = 1EDI60N12AF-DS_1
YC1-YC6 = CAP
U5 = SI8233BB-D-IS1
U104 U106-U114 = UCC5350MC
J3 = CON24A
J4 J5 = CON12A
J6 = CON2
J7 = CON10A
J8 = CON5
U15 U17-U24 = E1212S-2WR2_3
U16 U29 U33 = MC78L05F-TP
U30 = E1212S-2WR2_1
C63 C66 = CAP_NP: value1: 800V
CT2 = TRNSFMR_29398_4
D8 = LED081_200MA_30V_BAT54A_SOT23
D61 D62 = FMMD6100_SOT_0
T1 = HEATSINK_11
U3 = LM293A: Package: 3
U4 = LM293A: Package: 4
Q60 = FMMT718_SOT
U10 = Si8661_3
U34 = LM293A: Package: 5
U35 = 1EDI60N12AF-DS_2

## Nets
+5V_A: C146.2 C147.2 C596.2 C610.2 C611.1 R240.2 R242.2 R245.1 R246.1 R573.1 R596.1 U16.1(Vout)
-3V_PSW1: C37.2 C38.2 C45.2 C46.2 C141.2 C142.2 C143.2 C525.2 C614.2 D47.1(ANODE) U5.9(GNDB) U15.5(-Vout) U106.8(VEE2) ZD13.1(ANODE) ZD14.1(ANODE)
-3V_PSW2: C41.2 C162.2 C163.2 C499.2 C613.2 U17.5(-Vout) U104.8(VEE2) ZD35.1(ANODE)
-3V_PSW3: C33.2 C164.2 C165.2 C496.2 C524.2 D48.1(ANODE) U5.14(GNDA) U18.5(-Vout) ZD36.1(ANODE)
-3V_PSW4: C189.2 C479.2 C547.2 C549.2 C561.2 C563.2 U21.5(-Vout) U107.8(VEE2) U109.8(VEE2) ZD41.1(ANODE)
-3V_PSW5: C186.2 C191.2 C537.2 C542.2 U19.5(-Vout) U108.8(VEE2) ZD37.1(ANODE)
-3V_PSW7: C187.2 C188.2 C552.2 C556.2 U20.5(-Vout) U110.8(VEE2) ZD38.1(ANODE)
-3V_PSW9: C202.2 C209.2 C566.2 C570.2 U22.5(-Vout) U112.8(VEE2) ZD39.1(ANODE)
-3V_PSW10: C216.2 C483.2 C575.2 C577.2 C589.2 C591.2 U24.5(-Vout) U111.8(VEE2) U113.8(VEE2) ZD42.1(ANODE)
-3V_PSW11: C214.2 C215.2 C580.2 C584.2 U23.5(-Vout) U114.8(VEE2) ZD40.1(ANODE)
AGND: C1.2 C26.1 C27.1 C35.2 C36.2 C39.2 C40.2 C43.2 C44.2 C47.2 C48.2 C84.1 C88.2 C93.2 C101.2 C102.1 C137.2 C138.2 C139.2 C140.2 C151.2 C152.2 C156.2 C157.2 C158.2 C159.2 C160.2 C161.2 C170.2 C173.2 C174.2 C175.2 C177.2 C178.2 C179.2 C180.2 C181.2 C182.2 C183.2 C184.2 C234.1 C235.1 C236.1 C237.1 C238.1 C241.2 C242.2 C246.2 C247.2 C248.1 C284.1 C478.2 C530.2 C531.2 C532.2 C533.2 C540.2 C541.2 C543.2 C544.2 C550.2 C551.2 C554.2 C555.2 C557.2 C558.2 C592.2 C594.2 C595.1 C597.1 C598.2 C601.2 C602.2 C603.1 C604.1 C605.2 C606.2 C607.2 C608.2 C612.2 J3.2 J3.3 J3.4 J3.21 J5.6 J5.8 J7.6 J7.9 Q61.2(E) R8.2 R67.2 R68.2 R69.2 R70.2 R72.2 R73.2 R136.1 R539.1 R548.2 R550.2 R552.2 R554.2 U2.4(V-) U4.4(V-) U5.4(GNDI) U9.3(A) U10.8(GND1) U15.2(-Vin) U17.2(-Vin) U18.2(-Vin) U19.2(-Vin) U20.2(-Vin) U21.2(-Vin) U29.2(GND) U30.4(GND) U35.5(GND) U55.3(A) U103.5(GND2) U104.3(IN-) U104.4(GND1) U106.3(IN-) U106.4(GND1) U107.3(IN-) U107.4(GND1) U108.3(IN-) U108.4(GND1) U109.3(IN-) U109.4(GND1) U110.3(IN-) U110.4(GND1)
AGND_N: C8.2 C29.1 C30.2 C144.1 C145.1 C146.1 C147.1 C153.2 C154.2 C155.2 C164.1 C165.1 C278.1 C279.2 C280.2 C281.2 C282.1 C496.1 C497.2 C524.1 C596.1 C599.1 C610.1 C611.2 D2.3(AC_IN_2) Q4.3(SOURCE) Q5.2(DRAIN) Q60.3(C) R33.1 R41.2 R42.2 R44.2 R46.2 R47.2 R241.1 R243.2 U16.2(GND) U18.6(COM) U34.4(V-) U103.3(VIN-) U103.4(GND1) ZD36.2(CATHODE)
GND_EARTH: CON1.2 MH1.1 YC1.2 YC2.2 YC3.2 YC4.1 YC5.1 YC6.1
P6.5V: C234.2 C235.2 C236.2 J7.10 U29.3(Vin)
PGND: C9.2 C10.2 C11.2 C12.2 C13.2 C14.2 C15.2 C16.2 C17.2 C18.2 C24.2 C34.2 C37.1 C81.1 C82.1 C87.1 C89.2 C90.2 C92.2 C96.2 C99.1 C270.2 C271.2 C272.2 C273.2 C274.2 C275.2 C276.2 C277.2 C525.1 CB6.2 CB7.2 D2.4(DC_OUT_MINUS) Q5.3(SOURCE) Q6.2(S) Q7.2(S) R54.1 R66.2 R110.2 R111.2 R112.2 R113.2 R123.2 R129.1 R135.2 ZD13.2(CATHODE)
SGND: C100.2 C103.1 C195.2 C196.2 C197.2 C199.2 C203.2 C204.2 C205.2 C207.2 C210.2 C211.2 C212.2 C213.2 C256.1 C257.1 C258.1 C260.1 C261.1 C564.2 C565.2 C568.2 C569.2 C571.2 C572.2 C578.2 C579.2 C582.2 C583.2 C585.2 C586.2 J4.3 J4.6 J4.10 J8.5 R556.2 R558.2 R560.2 R563.2 U10.9(GND2) U22.2(-Vin) U23.2(-Vin) U24.2(-Vin) U33.2(GND) U111.3(IN-) U111.4(GND1) U112.3(IN-) U112.4(GND1) U113.3(IN-) U113.4(GND1) U114.3(IN-) U114.4(GND1)
_PFCREF1.6V: C28.1 R537.2 U2.1(OUT) U2.2(-IN)
_PREF1.6V: R119.1 U4.1(OUT) U4.2(-IN)
AC_L: D2.2(AC_IN_1) RLY1.3(COMMON) RV2.1 T1.21(AC_L_) XC4.1
AC_L_Samp: CL2.4(P12) R14.1 RLY1.4(NO) RV1.2 XC3.1 YC3.1
AC_L_Samp_D: J3.10 R16.2
AC_N_D: J3.12 R22.2
ACL1: CL1.4(P12) CL2.1(P11) XC2.1 YC1.1
ACN1: CL1.3(P22) CL2.2(P21) XC2.2 YC4.2
AD_DC_CUR: C94.2 J3.16 R132.2 U4.7(OUT)
CAN5V_GND: J4.2 J8.2
CAN_5V: J4.4 J8.1
ClampA: R216.2 R217.2 R602.1 R604.1 U104.7(CLAMP)
ClampB: R218.2 R219.2 R603.1 R605.1 U106.7(CLAMP)
ClampQ8: C53.1 Q8.4(G) R78.1 R82.2 U112.7(CLAMP)
ClampQ9: C54.1 Q9.4(G) R79.2 R83.2 U114.7(CLAMP)
ClampQ10: C56.1 Q10.4(G) R80.1 R85.2 R564.1 U108.7(CLAMP)
ClampQ11: C57.1 Q11.4(G) R81.2 R86.2 R565.2 U110.7(CLAMP)
ClampQ12: C76.1 Q12.4(G) R94.1 R99.2 U111.7(CLAMP)
ClampQ13: C77.1 Q13.4(G) R95.2 R100.2 U113.7(CLAMP)
ClampQ14: C79.1 Q14.4(G) R97.1 R103.2 R566.1 U107.7(CLAMP)
ClampQ15: C80.1 Q15.4(G) R98.2 R104.2 R567.2 U109.7(CLAMP)
DC_14V_input: C593.1 J6.2 J7.1
DCOCP: D8.3 J3.18
DCPWM1A_1H: J5.4 R551.1
DCPWM1A_1L: J5.2 R549.1
DCPWM2A_2H: J5.7 R555.1
DCPWM2A_2L: J5.5 R553.1
DRV_L_G: C176.2 C189.1 C479.1 C480.2 C481.2 C545.2 C547.1 C559.2 C561.1 R541.1 R542.2 U21.6(COM) ZD41.2(CATHODE)
DRVA: D57.2(CATHODE) R80.2 U108.6(OUT)
DRVA_G: C56.2 C166.2 C167.2 C168.2 C186.1 C191.1 C536.2 C537.1 Q10.3(GS) R85.1 U19.6(COM) ZD37.2(CATHODE)
DRVB: D59.2(CATHODE) R97.2 U107.6(OUT)
DRVC: D58.2(CATHODE) R81.1 U110.6(OUT)
DRVC_G: C57.2 C169.2 C171.2 C172.2 C187.1 C188.1 C552.1 C553.2 Q11.3(GS) R86.1 U20.6(COM) ZD38.2(CATHODE)
DRVD: D60.2(CATHODE) R98.1 U109.6(OUT)
DRVSA: R78.2 U112.6(OUT)
DRVSB: R94.2 U111.6(OUT)
DRVSC: R79.1 U114.6(OUT)
DRVSD: R95.1 U113.6(OUT)
HM1: Q10.2(S) Q14.1(D) T1.9(T_pri_1)
HM2: Q11.2(S) Q15.1(D) T1.19(Cr_pri_3)
HM3: Q8.2(S) Q12.1(D) T1.7(T_sec_2)
HM4: Q9.2(S) Q13.1(D) T1.20(Cr_sec_3)
IGND: C593.2 J6.1 J7.2
IPFC: CL2.3(P22) R20.1 R41.1 R42.1 R44.1 R46.1 R47.1 R62.2 R244.2 XC3.2 XC4.2 YC6.2
IPFCSAMPLE: C31.2 J3.17 R65.1 U2.7(OUT)
L: CON1.1 F1.1 F2.1 YC2.1
N: CL1.2(P21) CON1.3 R11.1 R12.1 VAR1.1 XC5.2 YC5.2
PCs+: C81.2 Q14.2(S) Q15.2(S) R110.1 R111.1 R112.1 R113.1 R117.2 R120.2 R138.2
PFC-FB: J3.23 R43.1
PFC-VO: J3.24 R45.1
PFC_G_A: C148.2 C149.2 C150.2 C162.1 C163.1 C498.2 C499.1 C613.1 R34.1 R35.1 U17.6(COM) ZD35.2(CATHODE)
PFC_G_B: C42.2 C45.1 C614.1 R56.1 R60.1 R75.2 R234.2 ZD14.2(CATHODE)
PFC_L: Q2.2(S) Q3.2(S) Q6.1(D) Q7.1(D) T1.2(Lpfc)
PFC_OCP: J3.15 R248.1
PFCDRVA: R27.1 R28.1 U104.6(OUT)
PFCDRVB: R51.1 R52.1 U106.6(OUT)
PFCDRVC: R29.1 U5.15(VOA)
PFCDRVD: R48.1 U5.10(VOB)
PFCREF1.6V: C478.1 C592.1 R538.2 R540.2 U2.3(+IN) U55.2(K)
PREF1.6V: C93.1 R126.2 R128.2 U4.3(+IN) U9.2(K)
PWM1A: J3.11 R71.1
PWM1B: J3.5 R74.1
PWM1C: J3.7 R251.1
PWM1D: J3.9 R250.1
RLYCTRL1: J3.22 R5.2
SPGND: C59.2 C63.2 C66.2 C72.2 C78.2 C267.2 C268.2 C269.2 CON2.3 Q12.2(S) Q13.2(S) R107.2
SR-PWM-A: J5.9 R141.2
SR-PWM-A-S: R142.2 R559.1
SR-PWM-B: J5.10 R143.2
SR-PWM-B-S: R144.2 R557.1
SR-PWM-C: J5.11 R145.2
SR-PWM-C-S: R146.2 R562.1
SR-PWM-D: J5.12 R147.2
SR-PWM-D-S: R148.2 R561.1
SR_DETA_Pri: D61.2(C2) D62.2(C2) J5.1 R568.2
SR_DETB_Pri: D61.1(C1) D62.1(C1) J5.3 R568.1
SR_L_G: C206.2 C216.1 C482.2 C483.1 C484.2 C573.2 C575.1 C587.2 C589.1 R543.1 R544.2 U24.6(COM) ZD42.2(CATHODE)
SRA_G: C53.2 C192.2 C193.2 C194.2 C202.1 C209.1 C566.1 C567.2 Q8.3(GS) R82.1 U22.6(COM) ZD39.2(CATHODE)
SRC_G: C54.2 C198.2 C200.2 C201.2 C214.1 C215.1 C580.1 C581.2 Q9.3(GS) R83.1 U23.6(COM) ZD40.2(CATHODE)
VDCLow+15V: C176.1 C480.1 C481.1 R588.2 R590.2 U21.7(+Vout)
VLow+15V: C34.1 C42.1 C136.1 C141.1 C143.1 R66.1 R75.1 R234.1 R577.2 R581.2 U15.7(+Vout)
VO1+: J4.11 R570.2
VO2+: J4.8 R118.2
VO+: C55.1 C58.1 C59.1 C63.1 C66.1 F3.1 Q8.1(D) Q9.1(D) R84.1 R114.1 R571.1
VP+5V: C237.2 C238.2 C246.1 C247.1 C594.1 C595.2 C597.2 C598.1 C601.1 C602.1 C603.2 C604.2 C605.1 C606.1 C607.1 C608.1 J3.20 R126.1 R134.2 R540.1 R545.1 R572.1 R574.1 R575.1 R578.1 R579.1 R582.2 R583.2 R584.1 R585.1 R586.1 R587.1 R597.2 U29.1(Vout) U30.2(IN)
VP+15V: C1.1 C137.1 C138.1 C151.1 C156.1 C157.1 C158.1 C170.1 C173.1 C177.1 C178.1 C181.1 C182.1 J3.14 J7.5 R3.2 R181.2 R182.2 R183.2 R184.2 R185.2 R186.2
VP+15V_DCDCA: C166.1 C167.1 C168.1 R591.2 U19.7(+Vout)
VP+15V_DCDCB: C169.1 C171.1 C172.1 R589.2 U20.7(+Vout)
VP+15V_HF_PFC: C148.1 C149.1 C150.1 R580.2 U17.7(+Vout)
VP-5V: C88.1 C241.1 C242.1 J3.19 R122.2 U3.4(V-) U30.1(OUT)
VPFC: C9.1 C10.1 C11.1 C12.1 C13.1 C14.1 C15.1 C16.1 C17.1 C18.1 C270.1 C271.1 C272.1 C273.1 C274.1 C275.1 C276.1 C277.1 CB6.1 CB7.1 D2.1(DC_OUT_PLUS) Q2.1(D) Q3.1(D) Q4.2(DRAIN) Q10.1(D) Q11.1(D) R30.2 R38.2
VPFC_LF+15V: C144.2 C145.2 C153.1 C154.1 C155.1 C599.2 R576.2 U16.3(Vin) U18.7(+Vout)
Vs+5V: C100.1 C258.2 C260.2 C261.2 J4.7 R139.2 R598.1 R599.1 R600.1 R601.1 U33.1(Vout)
VS+15V: C195.1 C199.1 C203.1 C204.1 C210.1 C211.1 C256.2 C257.2 J4.1 J8.4 R187.2 R188.2 R189.2 U33.3(Vin)
VS+15V_DCDCA: C192.1 C193.1 C194.1 R592.2 U22.7(+Vout)
VS+15V_DCDCB: C198.1 C200.1 C201.1 R594.2 U23.7(+Vout)
VSLow+15V: C206.1 C482.1 C484.1 R593.2 R595.2 U24.7(+Vout)
N10486979: C6.2 Q2.3(GS) R31.1 R34.2
N10631533: C6.1 Q2.4(G) R31.2 R602.2
N15409465: CL1.1(P11) F1.2 F2.2 R6.2 R7.2 VAR1.2 XC5.1
N15414859: D1.2(K) R1.1 RLY1.1(COIL2)
N15414880: Q61.3(C) R4.2 RLY1.2(COIL1)
N15816850: R9.1 R10.1 R11.2 R12.2
N15816858: R6.1 R7.1 R9.2 R10.2
N16123691: C267.1 C268.1 C269.1 CON2.1 F3.2
N16148248: R84.2 R89.1
N16148380: C55.2 C58.2 C72.1 C78.1 R93.2 R96.1
N16148534: R90.2 R93.1
N16148538: R89.2 R90.1
N16148540: R96.2 R101.1
N16148544: R102.2 R107.1
N16320789: R101.2 R102.1
N16587331: C7.2 Q3.3(GS) R32.1 R35.2
N16587391: C7.1 Q3.4(G) R32.2 R604.2
N16589757: C25.2 Q7.3(GS) R55.1 R60.2
N16589837: C25.1 Q7.4(G) R55.2 R603.2
N16589901: C23.2 Q6.3(GS) R53.1 R56.2
N16589961: C23.1 Q6.4(G) R53.2 R605.2
N16599678: C8.1 D48.2(CATHODE) Q4.1(GATE) R29.2 R33.2
N16600162: C24.1 D47.2(CATHODE) Q5.1(GATE) R48.2 R54.2
N16674941: C79.2 Q14.3(GS) R103.1 R541.2
N16677707: C80.2 Q15.3(GS) R104.1 R542.1
N16765027: C102.2 R140.1 U10.1(VDD1)
N16765075: C101.1 R140.2 R545.2
N16767690: C103.2 R139.1 U10.16(VDD2)
N16833658: R141.1 U10.2(A1)
N16833676: R143.1 U10.3(A2)
N16833742: R145.1 U10.4(A3)
N16833760: R147.1 U10.5(A4)
N16833940: R142.1 U10.15(B1)
N16833942: R144.1 U10.14(B2)
N16834016: R146.1 U10.13(B3)
N16834018: R148.1 U10.12(B4)
N17093919: R2.2 R3.1
N17093922: R1.2 R2.1
N17243036: C284.2 Q61.1(B) R5.1 R8.1
N17244938: R15.2 R16.1
N17244999: R14.2 R15.1
N17245029: R20.2 R21.1
N17245032: R21.2 R22.1
N17252696: C30.1 R62.1 U103.2(VIN+)
N17252758: C29.2 R573.2 U103.1(VDD1)
N17252921: C27.2 R574.2 U103.8(VDD2)
N17253061: R63.2 U103.7(VOUT+)
N17253066: R64.2 U103.6(VOUT-)
N17253305: C28.2 R63.1 R537.1 U2.5(+IN)
N17253318: C31.1 R64.1 R65.2 U2.6(-IN)
N17253751: C26.2 R572.2 U2.8(V+)
N17259772: R30.1 R37.2
N17259775: R37.1 R39.2
N17259778: R39.1 R43.2
N17259967: R38.1 R40.2
N17259969: R40.1 R45.2
N17264035: C76.2 Q12.3(GS) R99.1 R543.2
N17264090: C77.2 Q13.3(GS) R100.1 R544.1
N17266948: R114.2 R115.1
N17266951: R115.2 R118.1
N17268549: C82.2 C83.2 R116.2 R117.1 U3.5(+IN)
N17268684: D8.1 R116.1 U3.7(OUT)
N17268693: C83.1 C87.2 R122.1 R123.1 U3.6(-IN)
N17268930: C248.2 R582.1 U3.8(V+)
N17268988: C92.1 C97.2 R127.2 R129.2 R134.1 U3.3(+IN)
N17269030: C97.1 C99.2 R138.1 U3.2(-IN)
N17269076: D8.2 R127.1 U3.1(OUT)
N17269867: C89.1 R120.1 R121.2
N17269877: C90.1 C91.1 R119.2 R121.1 U4.5(+IN)
N17270011: C91.2 C94.1 C96.1 R130.1 R132.1 U4.6(-IN)
N17270029: R130.2 R135.1
N17270191: C84.2 R583.1 U4.8(V+)
N17272262: R128.1 R136.2 U9.1(REF)
N17277038: T1.3(Lr_sec_2) T1.5(Cr_sec_2) T1.6(Cr_sec_1)
N17288635: C35.1 R67.1 R251.2 U5.1(VIA)
N17288650: C36.1 R68.1 R250.2 U5.2(VIB)
N17289174: C39.1 C40.1 R575.2 U5.3(VDDII) U5.8(VDDI)
N17289191: R69.1 U5.5(DISABLE)
N17289200: R70.1 U5.6(DT)
N17289613: C33.1 C497.1 R576.1 U5.16(VDDA)
N17289747: C38.1 R577.1 U5.11(VDDB)
N17291315: C46.1 R581.1 U106.5(VCC2)
N17329322: C245.1 U30.5(C1+)
N17329326: C245.2 U30.3(C1-)
N17381506: R27.2 R216.1
N17381622: R52.2 R218.1
N17381677: R51.2 R219.1
N17452823: C136.2 C142.1 U15.6(COM)
N17452839: C139.1 C140.1 R181.1 U15.1(+Vin)
N17452887: C159.1 C160.1 R183.1 U18.1(+Vin)
N17453218: C152.1 C161.1 R182.1 U17.1(+Vin)
N17453412: C205.1 C207.1 R188.1 U23.1(+Vin)
N17453587: C196.1 C197.1 R187.1 U22.1(+Vin)
N17453815: C212.1 C213.1 R189.1 U24.1(+Vin)
N17454032: C183.1 C184.1 R186.1 U21.1(+Vin)
N17454238: C174.1 C175.1 R184.1 U19.1(+Vin)
N17454469: C179.1 C180.1 R185.1 U20.1(+Vin)
N17461429: C281.1 R244.1 R245.2 U34.2(-IN) U34.5(+IN)
N17461431: C278.2 R240.1 R243.1 U34.3(+IN)
N17461459: C280.1 R241.2 R242.1 U34.6(-IN)
N17461635: C279.1 R239.2 R596.2 U34.8(V+)
N17461650: C282.2 Q60.1(B) R239.1 U34.1(OUT) U34.7(OUT)
N17461720: Q60.2(E) U35.3(VF-)
N17461740: R246.2 U35.2(VF+)
N17461769: R247.1 U35.7(VB)
N17461771: C612.1 R247.2 R597.1 U35.8(VCC)
N17461781: R248.2 U35.6(VO)
N17577735: R538.1 R539.2 U55.1(REF)
N17603041: T1.12(Lr_pri_1) T1.13(Cr_pri_2) T1.14(Cr_pri_1)
N17746491: C530.1 C531.1 R578.2 U104.1(VCC1)
N17747250: C43.1 R71.2 R72.1 U104.2(IN+)
N17749975: C47.1 C48.1 R579.2 U106.1(VCC1)
N17750019: C44.1 R73.1 R74.2 U106.2(IN+)
N17751858: C41.1 C498.1 R580.1 U104.5(VCC2)
N17785545: C532.1 C533.1 R584.2 U108.1(VCC1)
N17785579: C544.1 R550.1 R551.2 U108.2(IN+)
N17785699: C540.1 C541.1 R585.2 U107.1(VCC1)
N17785727: C543.1 R548.1 R549.2 U107.2(IN+)
N17785767: C536.1 C542.1 R591.1 U108.5(VCC2)
N17785926: C545.1 C549.1 R590.1 U107.5(VCC2)
N17788175: C550.1 C551.1 R586.2 U110.1(VCC1)
N17788213: C558.1 R554.1 R555.2 U110.2(IN+)
N17788281: C554.1 C555.1 R587.2 U109.1(VCC1)
N17788301: C557.1 R552.1 R553.2 U109.2(IN+)
N17788345: C553.1 C556.1 R589.1 U110.5(VCC2)
N17788478: C559.1 C563.1 R588.1 U109.5(VCC2)
N17790300: C564.1 C565.1 R598.2 U112.1(VCC1)
N17790352: C572.1 R558.1 R559.2 U112.2(IN+)
N17790406: C568.1 C569.1 R599.2 U111.1(VCC1)
N17790440: C571.1 R556.1 R557.2 U111.2(IN+)
N17790484: C567.1 C570.1 R592.1 U112.5(VCC2)
N17790617: C573.1 C577.1 R593.1 U111.5(VCC2)
N17792648: C578.1 C579.1 R600.2 U114.1(VCC1)
N17792696: C586.1 R562.2 R563.1 U114.2(IN+)
N17792742: C582.1 C583.1 R601.2 U113.1(VCC1)
N17792776: C585.1 R560.1 R561.2 U113.2(IN+)
N17792812: C581.1 C584.1 R594.1 U114.5(VCC2)
N17792937: C587.1 C591.1 R595.1 U113.5(VCC2)
N17799215: D58.1(ANODE) R565.1
N17799359: D60.1(ANODE) R567.1
N17812200: CT12.1 D61.3(A)
N17812202: CT11.1 D62.3(A)
N17820985: R569.1 R571.2
N17820987: R569.2 R570.1
N17862384: RV1.1 RV2.2
N17862385: D1.1(A) R4.1
N17880901: D57.1(ANODE) R564.2
N17880973: D59.1(ANODE) R566.2
N17943029: R28.2 R217.1

Not connected (* = marked no-connect by the designer): CON2 2; J3 1 6 8 13; J4 5 9 12; J7 3 4 7 8; J8 3; T1 1(Lpfc) 4(Lr_sec_1) 8(T_sec_1) 10(T_pri_2) 11(Lr_pri_2) 15 16 17 18; U5 7(NC2) 12(NC) 13(NC1); U10 6(A5) 7(A6) 10(B6) 11(B5); U35 1(NC) 4(NC1)

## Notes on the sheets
sheet 1
- Inrush limit circuit
  Bypass the NTC at  bulk voltage >=90% Vac
  input with delay.
- EMI AND Inrush limiter
- Input: AC 90V to 265V
- EMI filter, MOV and fuse
- AC_L AC_N 35A trace before the Ecap.
- NTC&Relay based Inrush Current Limit
- INPUT VOLTAGE SAMPLE
- VPFC and PGND 20A trace after the Ecap.
- PFC AND INVERTER
- VPFC and PGND 35A trace before the Ecap.
- PGND and AGND single connection at Ecap
- PFC Current sample
- PK:1.357V
- RMS:0.8V
- MAX: RMS: 0.059V,PK,0.097V
- PCB Ver.: REV 3
- BOM Ver.: B
- Prepared by:
- .
- Kevin Xie
- Approved by:
- Frank Wei
sheet 2
- PCB Ver.: REV 3
- BOM Ver.: B
- Prepared by:
- Kevin Xie
- Approved by:
- Frank Wei
sheet 3
- The Rdson of the MOSFET of DCDC will depends on the final thermal data. 60mohm or 45mohm
- 385-425V 16A--20A
- VPFC and PGND 20A trace.
- Output current sensor
- VO and SGND 20A trace.
- SGND and SPGND single connection at Ecap
- 5m, Ipk=22.8A, Irms=15.735A
- Vsample_pk=0.115V, Vsample_rms=0.0875V
- DC OCP
- DC output voltage sample
- DC Current Sample
- BIAS voltage: 0.19V
- OCP Point: 42A
- Vsample_pk=2.591V+0.19V=2.78V
- Vsample_rms=1.788V+0.19V=1.978V
- G=22.72
- 450V--->2.885V
- 450V--->2.885V
- DC OCP
- PCs+ and AGND from sense resistor.   Differential signals, be parallel in PCB layout!
- PCB Ver.: REV 3
- BOM Ver.: B
- Prepared by:
- Kevin Xie
- Approved by:
- Frank Wei
sheet 4
- PFC OCP
- BIAS VOLTAGE: 0.45V
- NEAR DSP
- OCP Point:78A to be debug
- PCB Ver.: REV 3
- BOM Ver.: B
- Prepared by:
- Kevin Xie
- Approved by:
- Frank Wei
sheet 5
- PCB Ver.: REV 3
- BOM Ver.: B
- Prepared by:
- Kevin Xie
- Approved by:
- Frank Wei
sheet 6
- PCB Ver.: REV 3
- BOM Ver.: BB
- Prepared by:
- Kevin Xie
- Approved by:
- Frank Wei
sheet 7
- 12V--->+5V
- PFC power supply of current sample and driver
- Connect to  AUX power board
- DC Primary power supply for gate driver
- DC Secondary power supply for gate driver
- PCB Ver.: REV 3
- BOM Ver.: B
- Prepared by:
- Kevin Xie
- Approved by:
- Frank Wei
